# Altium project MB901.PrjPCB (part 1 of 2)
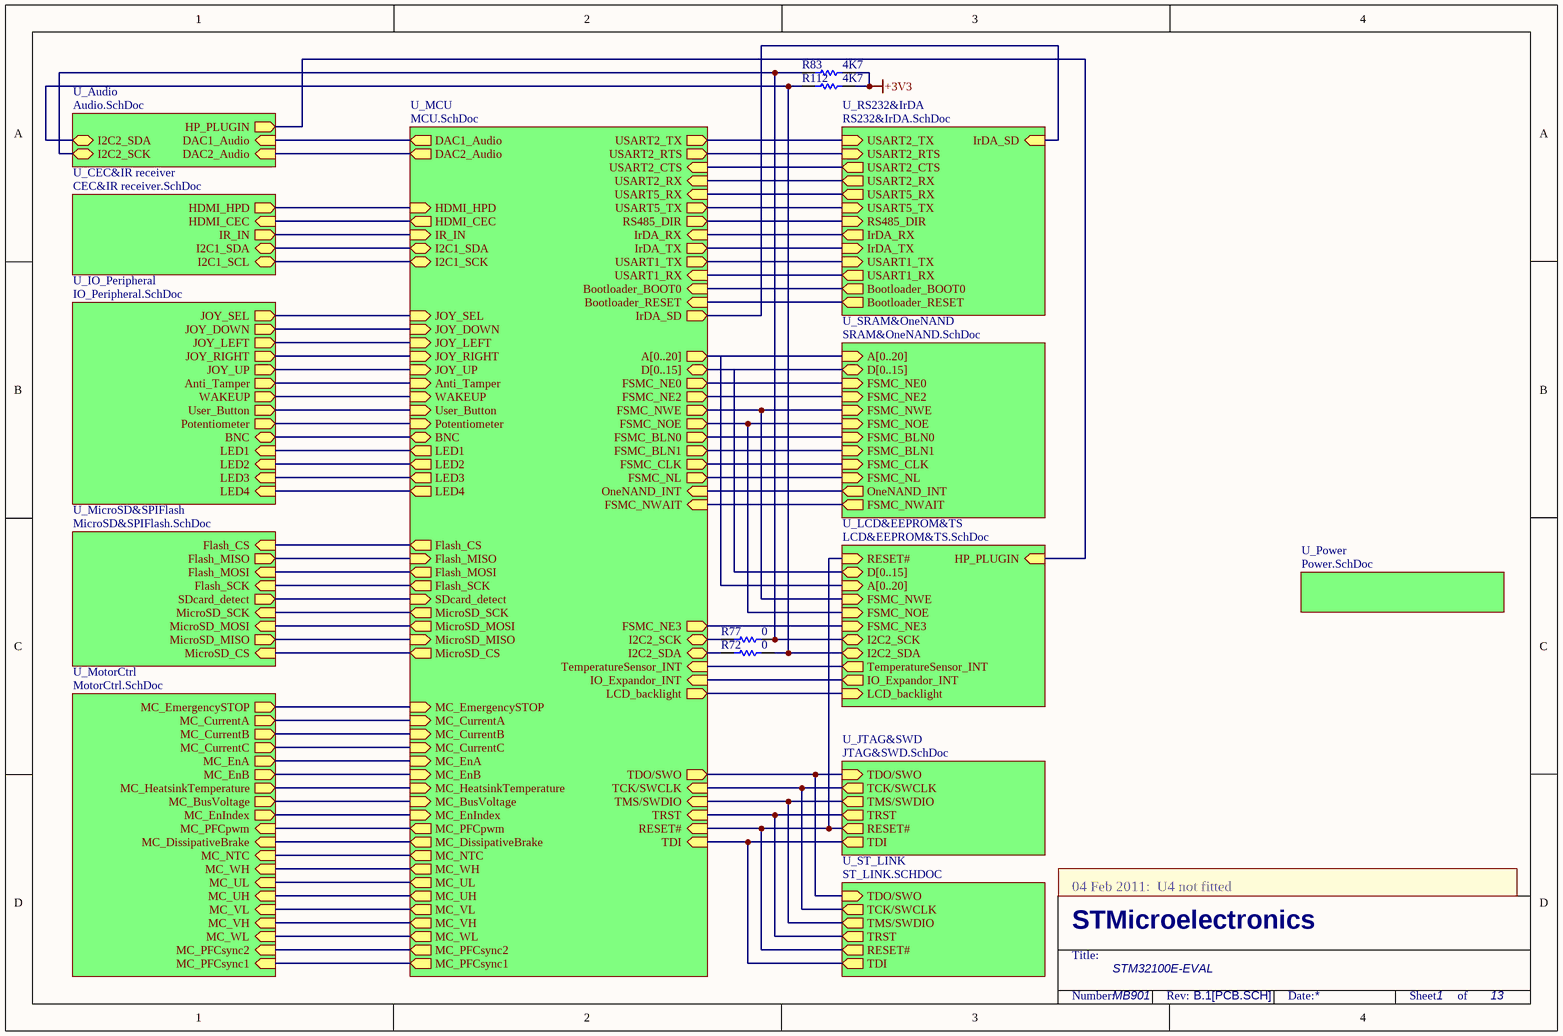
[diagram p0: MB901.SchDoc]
13 sheets, 331 parts. Net scope: hierarchical (ports join the sheet entries above them; power ports are global).
Board file: MB901.PCBDOC
Sheets:
  MB901.SchDoc
    U_Audio = Audio.SchDoc
    U_CEC&IR receiver = CEC&IR receiver.SchDoc
    U_IO_Peripheral = IO_Peripheral.SchDoc
    U_JTAG&SWD = JTAG&SWD.SchDoc
    U_LCD&EEPROM&TS = LCD&EEPROM&TS.SchDoc
    U_MCU = MCU.SchDoc
    U_MicroSD&SPIFlash = MicroSD&SPIFlash.SchDoc
    U_MotorCtrl = MotorCtrl.SchDoc
    U_Power = Power.SchDoc
    U_RS232&IrDA = RS232&IrDA.SchDoc
    U_SRAM&OneNAND = SRAM&OneNAND.SchDoc
    U_ST_LINK = ST_LINK.SCHDOC

## Sheet MB901.SchDoc
size A4; Revision: B.1[PCB.SCH]

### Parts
R72  0  [0603R]
R77  0  [0603R]
R83  4K7  [0603R]
R112  4K7  [0603R]

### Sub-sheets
U_Audio = Audio.SchDoc: DAC2_Audio (in), DAC1_Audio (in), I2C2_SCK (bidir), I2C2_SDA (bidir), HP_PLUGIN (out)
U_CEC&IR receiver = CEC&IR receiver.SchDoc: HDMI_CEC (in), I2C1_SCL (bidir), I2C1_SDA (bidir), HDMI_HPD (out), IR_IN (out)
U_IO_Peripheral = IO_Peripheral.SchDoc: JOY_SEL (out), JOY_DOWN (out), JOY_LEFT (out), JOY_RIGHT (out), JOY_UP (out), Anti_Tamper (out), WAKEUP (out), User_Button (out), LED4 (in), LED3 (in), LED1 (in), LED2 (in), BNC (bidir), Potentiometer (out)
U_JTAG&SWD = JTAG&SWD.SchDoc: TDI (out), RESET# (out), TRST (out), TMS/SWDIO (out), TCK/SWCLK (out), TDO/SWO (in)
U_LCD&EEPROM&TS = LCD&EEPROM&TS.SchDoc: RESET# (in), D[0..15] (bidir), A[0..20] (in), FSMC_NWE (in), FSMC_NOE (in), FSMC_NE3 (in), IO_Expandor_INT (out), I2C2_SCK (bidir), I2C2_SDA (bidir), TemperatureSensor_INT (out), LCD_backlight (in), HP_PLUGIN (in)
U_MCU = MCU.SchDoc: TDI (in), TMS/SWDIO (in), TCK/SWCLK (in), USART2_RX (in), USART2_TX (out), USART2_RTS (out), USART2_CTS (in), USART1_TX (out), USART1_RX (in), MC_EmergencySTOP (in), MC_UL (out), MC_DissipativeBrake (out), MC_EnA (in), MC_EnB (in), MC_EnIndex (in), WAKEUP (in), Flash_SCK (out), Flash_MISO (in), Flash_MOSI (out), BNC (bidir), TRST (in), TDO/SWO (out), MC_PFCsync1 (out), MC_WL (out), MC_VL (out), MC_NTC (out), MC_PFCpwm (out), Flash_CS (out), TemperatureSensor_INT (in), I2C2_SCK (bidir), I2C2_SDA (bidir), IrDA_RX (in), IrDA_TX (out), MC_CurrentA (in), MC_CurrentB (in), MC_CurrentC (in), MC_VH (out), MC_UH (out), MC_WH (out), MC_BusVoltage (in), MC_HeatsinkTemperature (in), Potentiometer (in), Anti_Tamper (in), RESET# (in), MC_PFCsync2 (out), FSMC_NE0 (out), FSMC_NWE (out), FSMC_NOE (out), FSMC_NWAIT (in), FSMC_BLN0 (out), User_Button (in), LED3 (out), LED1 (out), LED2 (out), JOY_SEL (in), JOY_DOWN (in), JOY_LEFT (in), JOY_RIGHT (in), JOY_UP (in), FSMC_NE2 (out), LED4 (out), D[0..15] (bidir), A[0..20] (out), FSMC_NE3 (out), FSMC_BLN1 (out), Bootloader_BOOT0 (in), Bootloader_RESET (in), MicroSD_SCK (out), MicroSD_MOSI (out), MicroSD_MISO (in), MicroSD_CS (out), IR_IN (in), USART5_RX (in), USART5_TX (out), HDMI_CEC (out), HDMI_HPD (in), RS485_DIR (out), FSMC_CLK (out), FSMC_NL (out), SDcard_detect (in), IO_Expandor_INT (in), OneNAND_INT (in), I2C1_SCK (bidir), I2C1_SDA (bidir), DAC2_Audio (out), DAC1_Audio (out), LCD_backlight (out), IrDA_SD (out)
U_MicroSD&SPIFlash = MicroSD&SPIFlash.SchDoc: Flash_CS (in), Flash_SCK (in), Flash_MISO (out), Flash_MOSI (in), MicroSD_CS (in), MicroSD_SCK (in), MicroSD_MOSI (in), MicroSD_MISO (out), SDcard_detect (out)
U_MotorCtrl = MotorCtrl.SchDoc: MC_EmergencySTOP (out), MC_CurrentA (out), MC_CurrentB (out), MC_CurrentC (out), MC_PFCsync1 (in), MC_PFCsync2 (in), MC_WL (in), MC_VH (in), MC_VL (in), MC_UH (in), MC_UL (in), MC_WH (in), MC_NTC (in), MC_DissipativeBrake (in), MC_PFCpwm (in), MC_EnA (out), MC_EnB (out), MC_HeatsinkTemperature (out), MC_BusVoltage (out), MC_EnIndex (out)
U_Power = Power.SchDoc: no entries
U_RS232&IrDA = RS232&IrDA.SchDoc: USART2_RX (out), USART2_TX (in), USART2_RTS (in), USART2_CTS (out), USART1_TX (in), USART1_RX (out), IrDA_RX (out), IrDA_TX (in), RS485_DIR (in), USART5_RX (out), USART5_TX (in), Bootloader_BOOT0 (out), Bootloader_RESET (out), IrDA_SD (in)
U_SRAM&OneNAND = SRAM&OneNAND.SchDoc: A[0..20] (in), D[0..15] (bidir), FSMC_NE0 (in), FSMC_NE2 (in), FSMC_NWE (in), FSMC_NOE (in), FSMC_BLN0 (in), FSMC_BLN1 (in), FSMC_NWAIT (out), FSMC_CLK (in), FSMC_NL (in), OneNAND_INT (out)
U_ST_LINK = ST_LINK.SCHDOC: TDI (out), TRST (out), TMS/SWDIO (out), TCK/SWCLK (out), TDO/SWO (in), RESET# (out)

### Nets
+3V3: R83.1 R112.1
PA0: sheet U_IO_Peripheral/WAKEUP, sheet U_MCU/WAKEUP
PA1: sheet U_MCU/USART2_RTS, sheet U_MCU/MC_EnB, sheet U_MotorCtrl/MC_EnB, sheet U_RS232&IrDA/USART2_RTS
PA2: sheet U_MCU/USART2_TX, sheet U_MCU/MC_EnIndex, sheet U_MotorCtrl/MC_EnIndex, sheet U_RS232&IrDA/USART2_TX
PA3: sheet U_MCU/USART2_RX, sheet U_RS232&IrDA/USART2_RX
PA4: sheet U_Audio/DAC1_Audio, sheet U_IO_Peripheral/BNC, sheet U_MCU/BNC, sheet U_MCU/DAC1_Audio
PA5: sheet U_Audio/DAC2_Audio, sheet U_MCU/Flash_SCK, sheet U_MCU/DAC2_Audio, sheet U_MicroSD&SPIFlash/Flash_SCK
PA6: sheet U_MCU/Flash_MISO, sheet U_MicroSD&SPIFlash/Flash_MISO
PA7: sheet U_MCU/MC_UL, sheet U_MCU/Flash_MOSI, sheet U_MicroSD&SPIFlash/Flash_MOSI, sheet U_MotorCtrl/MC_UL
PA8: sheet U_MCU/MC_UH, sheet U_MotorCtrl/MC_UH
PA9: sheet U_MCU/USART1_TX, sheet U_MCU/MC_VH, sheet U_MotorCtrl/MC_VH, sheet U_RS232&IrDA/USART1_TX
PA11: sheet U_MCU/IrDA_SD, sheet U_RS232&IrDA/IrDA_SD
PA12: sheet U_LCD&EEPROM&TS/IO_Expandor_INT, sheet U_MCU/IO_Expandor_INT
PA13: sheet U_JTAG&SWD/TMS/SWDIO, sheet U_MCU/TMS/SWDIO, sheet U_ST_LINK/TMS/SWDIO
PA14: sheet U_JTAG&SWD/TCK/SWCLK, sheet U_MCU/TCK/SWCLK, sheet U_ST_LINK/TCK/SWCLK
PA15: sheet U_JTAG&SWD/TDI, sheet U_MCU/TDI, sheet U_ST_LINK/TDI
PB0: sheet U_MCU/MC_VL, sheet U_MotorCtrl/MC_VL
PB1: sheet U_MCU/MC_WL, sheet U_MotorCtrl/MC_WL
PB3: sheet U_JTAG&SWD/TDO/SWO, sheet U_MCU/TDO/SWO, sheet U_ST_LINK/TDO/SWO
PB4: sheet U_JTAG&SWD/TRST, sheet U_MCU/TRST, sheet U_MCU/MC_PFCsync1, sheet U_MotorCtrl/MC_PFCsync1, sheet U_ST_LINK/TRST
PB5: sheet U_MCU/MC_PFCpwm, sheet U_MotorCtrl/MC_PFCpwm
PB6: sheet U_CEC&IR receiver/I2C1_SCL, sheet U_MCU/I2C1_SCK
PB8: sheet U_CEC&IR receiver/HDMI_CEC, sheet U_MCU/HDMI_CEC
PB9: sheet U_CEC&IR receiver/HDMI_HPD, sheet U_MCU/HDMI_HPD
PB10: R77.2 ; sheet U_MCU/I2C2_SCK
PB11: R72.2 ; sheet U_MCU/I2C2_SDA
PB12: sheet U_MCU/MC_NTC, sheet U_MotorCtrl/MC_NTC
PB13: sheet U_MCU/MicroSD_SCK, sheet U_MicroSD&SPIFlash/MicroSD_SCK
PB14: sheet U_MCU/MicroSD_MISO, sheet U_MicroSD&SPIFlash/MicroSD_MISO
PB15: sheet U_MCU/MicroSD_MOSI, sheet U_MicroSD&SPIFlash/MicroSD_MOSI
PC0: sheet U_MCU/MC_BusVoltage, sheet U_MotorCtrl/MC_BusVoltage
PC1: sheet U_MCU/MC_CurrentA, sheet U_MotorCtrl/MC_CurrentA
PC2: sheet U_MCU/MC_CurrentB, sheet U_MotorCtrl/MC_CurrentB
PC3: sheet U_MCU/MC_CurrentC, sheet U_MotorCtrl/MC_CurrentC
PC4: sheet U_IO_Peripheral/Potentiometer, sheet U_MCU/Potentiometer
PC5: sheet U_MCU/MC_HeatsinkTemperature, sheet U_MotorCtrl/MC_HeatsinkTemperature
PC6: sheet U_CEC&IR receiver/IR_IN, sheet U_MCU/IR_IN
PC7: sheet U_LCD&EEPROM&TS/LCD_backlight, sheet U_MCU/LCD_backlight
PC8: sheet U_MCU/MC_DissipativeBrake, sheet U_MotorCtrl/MC_DissipativeBrake
PC9: sheet U_MCU/RS485_DIR, sheet U_RS232&IrDA/RS485_DIR
PC10: sheet U_MCU/IrDA_TX, sheet U_RS232&IrDA/IrDA_TX
PC11: sheet U_MCU/IrDA_RX, sheet U_RS232&IrDA/IrDA_RX
PC12: sheet U_MCU/USART5_TX, sheet U_RS232&IrDA/USART5_TX
PC13: sheet U_IO_Peripheral/Anti_Tamper, sheet U_MCU/Anti_Tamper
PD2: sheet U_MCU/MC_PFCsync2, sheet U_MotorCtrl/MC_PFCsync2
PD3: sheet U_MCU/FSMC_CLK, sheet U_SRAM&OneNAND/FSMC_CLK
PD4: sheet U_LCD&EEPROM&TS/FSMC_NOE, sheet U_MCU/FSMC_NOE, sheet U_SRAM&OneNAND/FSMC_NOE
PD5: sheet U_LCD&EEPROM&TS/FSMC_NWE, sheet U_MCU/FSMC_NWE, sheet U_SRAM&OneNAND/FSMC_NWE
PD6: sheet U_MCU/FSMC_NWAIT, sheet U_SRAM&OneNAND/FSMC_NWAIT
PD7: sheet U_MCU/FSMC_NE0, sheet U_SRAM&OneNAND/FSMC_NE0
PE0: sheet U_MCU/FSMC_BLN0, sheet U_SRAM&OneNAND/FSMC_BLN0
PE1: sheet U_MCU/FSMC_BLN1, sheet U_SRAM&OneNAND/FSMC_BLN1
PE6: sheet U_MCU/Flash_CS, sheet U_MicroSD&SPIFlash/Flash_CS
PF6: sheet U_IO_Peripheral/LED1, sheet U_MCU/LED1
PF7: sheet U_IO_Peripheral/LED2, sheet U_MCU/LED2
PF8: sheet U_IO_Peripheral/LED3, sheet U_MCU/LED3
PF9: sheet U_IO_Peripheral/LED4, sheet U_MCU/LED4
PF10: sheet U_MCU/OneNAND_INT, sheet U_SRAM&OneNAND/OneNAND_INT
PF11: sheet U_MCU/SDcard_detect, sheet U_MicroSD&SPIFlash/SDcard_detect
PG6: sheet U_MCU/MicroSD_CS, sheet U_MicroSD&SPIFlash/MicroSD_CS
PG7: sheet U_IO_Peripheral/JOY_SEL, sheet U_MCU/JOY_SEL
PG8: sheet U_IO_Peripheral/User_Button, sheet U_MCU/User_Button
PG10: sheet U_MCU/FSMC_NE2, sheet U_SRAM&OneNAND/FSMC_NE2
PG11: sheet U_IO_Peripheral/JOY_DOWN, sheet U_MCU/JOY_DOWN
PG12: sheet U_LCD&EEPROM&TS/FSMC_NE3, sheet U_MCU/FSMC_NE3
PG13: sheet U_IO_Peripheral/JOY_RIGHT, sheet U_MCU/JOY_RIGHT
PG14: sheet U_IO_Peripheral/JOY_LEFT, sheet U_MCU/JOY_LEFT
PG15: sheet U_IO_Peripheral/JOY_UP, sheet U_MCU/JOY_UP
RESET#: sheet U_JTAG&SWD/RESET#, sheet U_LCD&EEPROM&TS/RESET#, sheet U_MCU/RESET#, sheet U_ST_LINK/RESET#
NetC13_2: sheet U_MCU/MC_EnA, sheet U_MotorCtrl/MC_EnA
NetCN1_11: sheet U_MCU/MC_WH, sheet U_MotorCtrl/MC_WH
NetCN11_5: sheet U_Audio/HP_PLUGIN, sheet U_LCD&EEPROM&TS/HP_PLUGIN
NetJP3_2: sheet U_MCU/MC_EmergencySTOP, sheet U_MotorCtrl/MC_EmergencySTOP
NetJP4_3: sheet U_MCU/USART2_CTS, sheet U_RS232&IrDA/USART2_CTS
NetJP5_1: sheet U_MCU/USART1_RX, sheet U_RS232&IrDA/USART1_RX
NetJP6_1: sheet U_MCU/FSMC_NL, sheet U_SRAM&OneNAND/FSMC_NL
NetJP6_3: sheet U_CEC&IR receiver/I2C1_SDA, sheet U_MCU/I2C1_SDA
NetJP7_2: sheet U_MCU/Bootloader_RESET, sheet U_RS232&IrDA/Bootloader_RESET
NetJP8_2: sheet U_MCU/Bootloader_BOOT0, sheet U_RS232&IrDA/Bootloader_BOOT0
NetJP9_1: sheet U_MCU/USART5_RX, sheet U_RS232&IrDA/USART5_RX
NetJP11_2: sheet U_LCD&EEPROM&TS/TemperatureSensor_INT, sheet U_MCU/TemperatureSensor_INT
NetR72_1: R72.1 R112.2 ; sheet U_Audio/I2C2_SDA, sheet U_LCD&EEPROM&TS/I2C2_SDA
NetR77_1: R77.1 R83.2 ; sheet U_Audio/I2C2_SCK, sheet U_LCD&EEPROM&TS/I2C2_SCK

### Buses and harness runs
bus sheet U_LCD&EEPROM&TS/A[0..20] = sheet U_MCU/A[0..20] = sheet U_SRAM&OneNAND/A[0..20]
bus sheet U_LCD&EEPROM&TS/D[0..15] = sheet U_MCU/D[0..15] = sheet U_SRAM&OneNAND/D[0..15]

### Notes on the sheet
- 04 Feb 2011:  U4 not fitted
- STM32100E-EVAL
- MB901
- 1
- 13

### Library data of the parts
R72 R77 R83 R112 = Res1: Resistor; Value: 1K

## Sheet Audio.SchDoc
size A4; Revision: B.1(PCB.SCH)
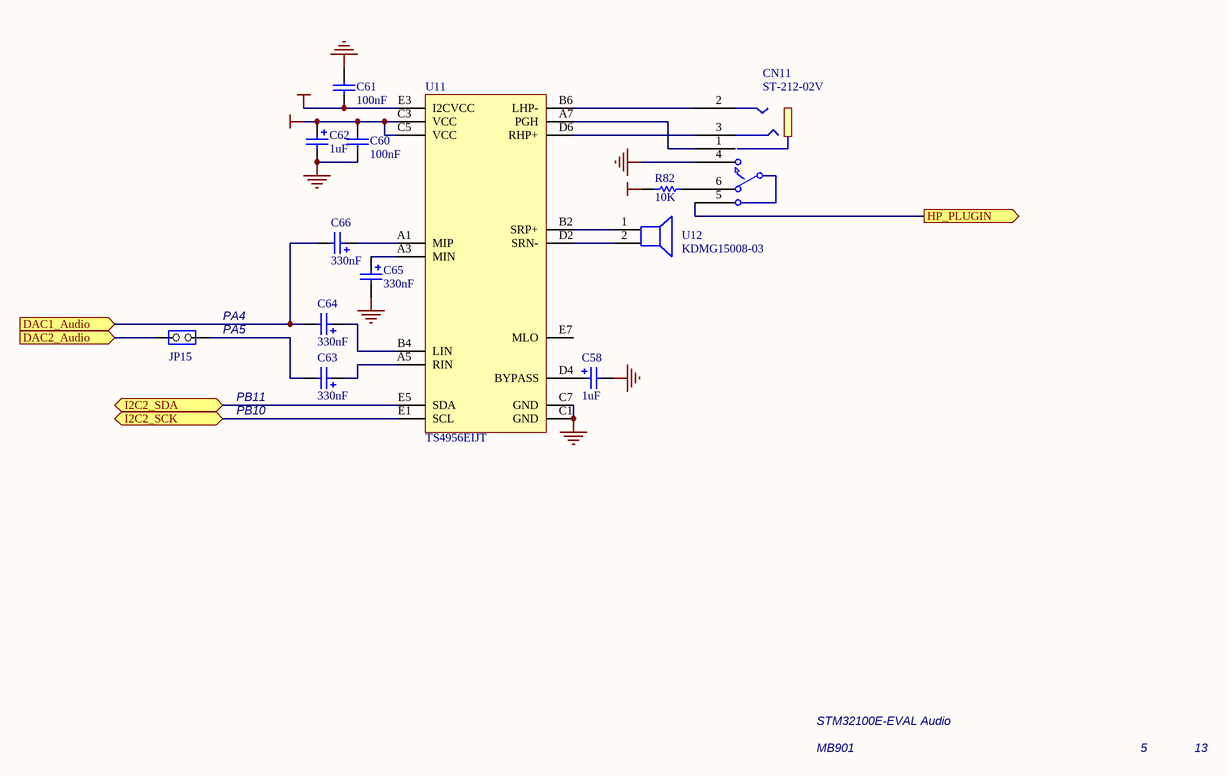
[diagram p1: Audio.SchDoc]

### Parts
C58  1uF  [TAN-A]
C60  100nF  [0402C]
C61  100nF  [0402C]
C62  1uF  [TAN-A]
C63  330nF  [0603C]
C64  330nF  [0603C]
C65  330nF  [0603C]
C66  330nF  [0603C]
CN11  ST-212-02V  [ST-212-02V]
JP15  (no value)  [SIP2]
R82  10K  [0402R]
U11  TS4956EIJT  [18-bump flip-chip]
U12  KDMG15008-03  [KS1508]

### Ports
DAC1_Audio (in), DAC2_Audio (in), HP_PLUGIN (out), I2C2_SCK (bidir), I2C2_SDA (bidir)

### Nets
+3V3: C61.1 R82.1 U11.E3(I2CVCC)
+5V: C60.1 C62.1 U11.C3(VCC) U11.C5(VCC)
GND: C58.2 C60.2 C61.2 C62.2 C65.2 CN11.4 U11.C1(GND) U11.C7(GND)
PA4: C64.2 C66.2 ; port DAC1_Audio
PA5: JP15.2(NO) ; port DAC2_Audio
NetC58_1: C58.1 U11.D4(BYPASS)
NetC63_1: C63.1 U11.A5(RIN)
NetC63_2: C63.2 JP15.1(COMMON)
NetC64_1: C64.1 U11.B4(LIN)
NetC65_1: C65.1 U11.A3(MIN)
NetC66_1: C66.1 U11.A1(MIP)
NetCN11_1: CN11.1 U11.A7(PGH)
NetCN11_2: CN11.2 U11.B6(LHP-)
NetCN11_3: CN11.3 U11.D6(RHP+)
NetCN11_5: CN11.5 ; port HP_PLUGIN
NetCN11_6: CN11.6 R82.2
NetR72_1: U11.E5(SDA) ; port I2C2_SDA
NetR77_1: U11.E1(SCL) ; port I2C2_SCK
NetU11_B2: U11.B2(SRP+) U12.1(+)
NetU11_D2: U11.D2(SRN-) U12.2(-)

Not connected (* = marked no-connect by the designer): U11 E7(MLO)

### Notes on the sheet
- (near JP15) PA5
- (near JP15) PA4
- PB11
- PB10
- STM32100E-EVAL Audio
- MB901
- 5
- 13

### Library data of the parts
C58 C62-C66 = Cap Pol1: Polarized Capacitor (Radial); Value: 10uF
C60 C61 = CAP: Capacitor
JP15 = JP2
R82 = res1: Resistor; Value: 1K
U12 = Speaker: Loudspeaker

## Sheet CEC&IR receiver.SchDoc
size A4; Revision: B.1(PCB.SCH)
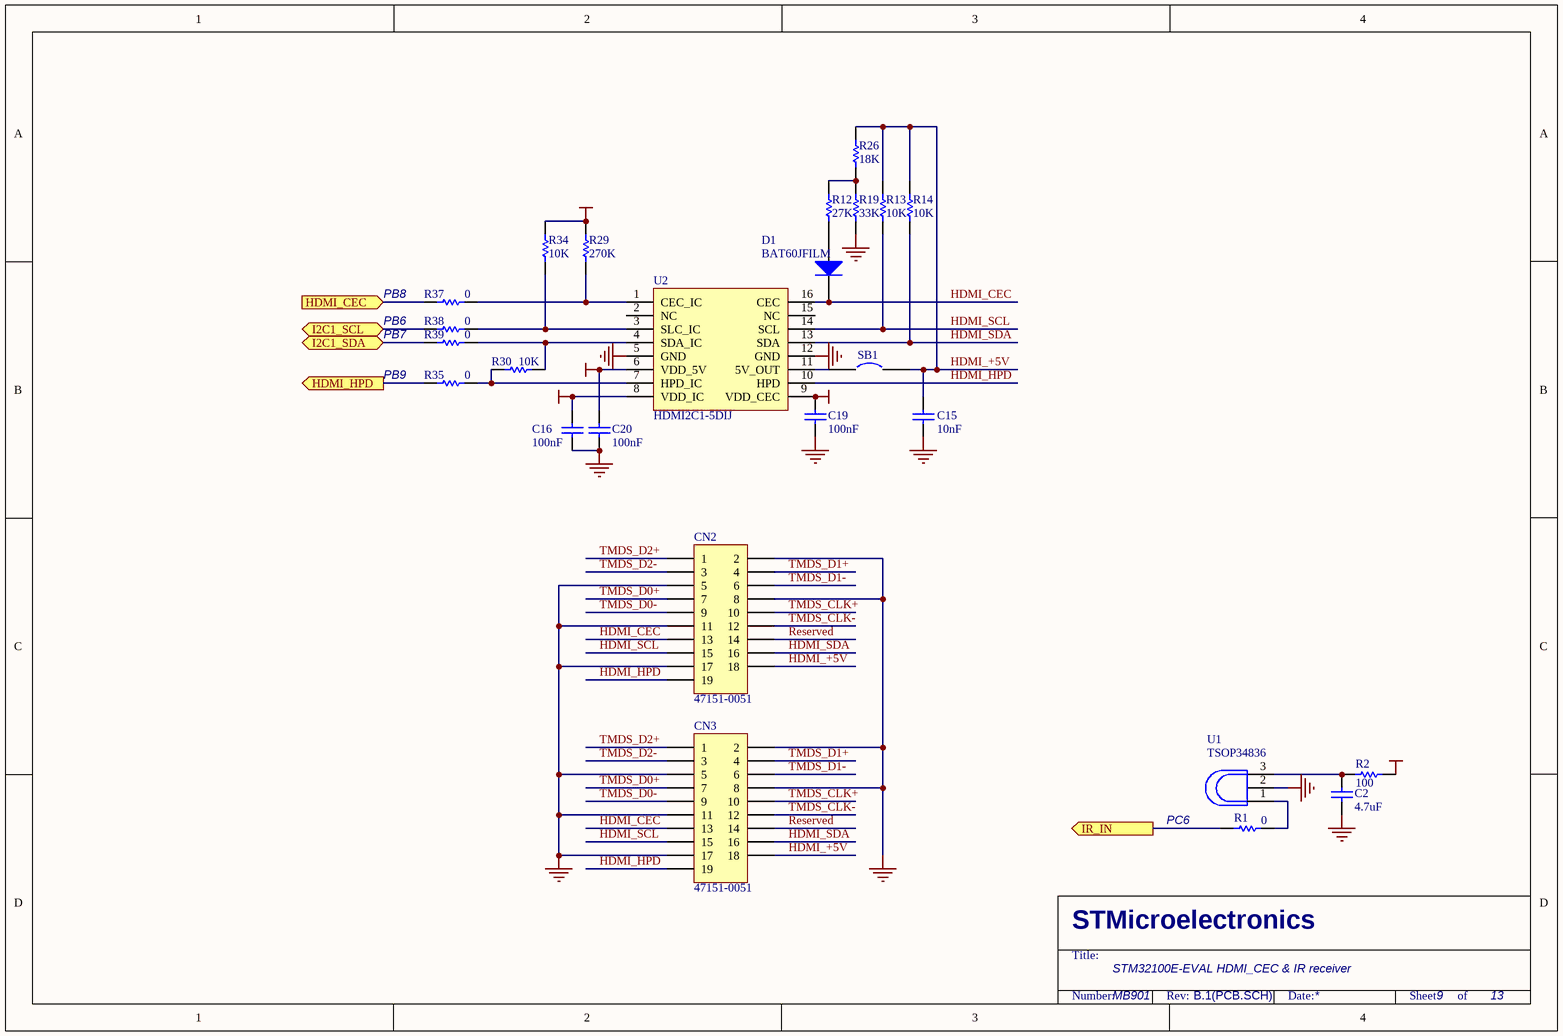
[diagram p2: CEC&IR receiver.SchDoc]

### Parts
C2  4.7uF  [1206C]
C15  10nF  [0603C]
C16  100nF  [0402C]
C19  100nF  [0402C]
C20  100nF  [0402C]
CN2  47151-0051  [0471510101]
CN3  47151-0051  [0471510101]
D1  BAT60JFILM  [SOD-323]
R1  0  [0603R]
R2  100  [0603R]
R12  27K  [0603R]
R13  10K  [0402R]
R14  10K  [0402R]
R19  33K  [0603R]
R26  18K  [0603R]
R29  270K  [0603R]
R30  10K  [0402R]
R34  10K  [0402R]
R35  0  [0603R]
R37  0  [0603R]
R38  0  [0603R]
R39  0  [0603R]
SB1  (no value)  [JP2_SMD]
U1  TSOP34836
U2  HDMI2C1-5DIJ  [QFN16(5*4)]

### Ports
HDMI_CEC (in), HDMI_HPD (out), I2C1_SCL (bidir), I2C1_SDA (bidir), IR_IN (out)

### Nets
+3V3: C16.1 C19.1 R2.2 R29.1 R34.1 U2.8(VDD_IC) U2.9(VDD_CEC)
+5V: C20.1 U2.6(VDD_5V)
GND: C2.2 C15.2 C16.2 C19.2 C20.2 CN2.2 CN2.5 CN2.8 CN2.11 CN2.17 CN3.2 CN3.5 CN3.8 CN3.11 CN3.17 R19.2 U1.2(GND) U2.5(GND) U2.12(GND)
HDMI_+5V: C15.1 CN2.18 CN3.18 R13.1 R14.1 R26.1 SB1.2
HDMI_CEC: CN2.13 CN3.13 D1.2(K) U2.16(CEC)
HDMI_HPD: CN2.19 CN3.19 U2.10(HPD)
HDMI_SCL: CN2.15 CN3.15 R13.2 U2.14(SCL)
HDMI_SDA: CN2.16 CN3.16 R14.2 U2.13(SDA)
PB6: R38.2 ; port I2C1_SCL
PB8: R37.2 ; port HDMI_CEC
PB9: R35.2 ; port HDMI_HPD
PC6: R1.1 ; port IR_IN
Reserved: CN2.14 CN3.14
TMDS_CLK+: CN2.10 CN3.10
TMDS_CLK-: CN2.12 CN3.12
TMDS_D0+: CN2.7 CN3.7
TMDS_D0-: CN2.9 CN3.9
TMDS_D1+: CN2.4 CN3.4
TMDS_D1-: CN2.6 CN3.6
TMDS_D2+: CN2.1 CN3.1
TMDS_D2-: CN2.3 CN3.3
NetC2_1: C2.1 R2.1 U1.3(Vs)
NetD1_1: D1.1(A) R12.2
NetJP6_3: R39.2 ; port I2C1_SDA
NetR1_2: R1.2 U1.1(OUT)
NetR12_1: R12.1 R19.1 R26.2
NetR29_2: R29.2 R37.1 U2.1(CEC_IC)
NetR30_1: R30.1 R35.1 U2.7(HPD_IC)
NetR30_2: R30.2 R39.1 U2.4(SDA_IC)
NetR34_2: R34.2 R38.1 U2.3(SLC_IC)
NetSB1_1: SB1.1 U2.11(5V_OUT)

Not connected (* = marked no-connect by the designer): U2 2(NC) 15(NC)

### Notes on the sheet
- PB8
- PB6
- PB7
- PB9
- PC6
- STM32100E-EVAL HDMI_CEC & IR receiver
- MB901
- 9
- 13

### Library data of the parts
C2 C16 C19 C20 = Cap: Capacitor; Value: 10nF
C15 = Cap: Capacitor
CN2 CN3 = Header 10X2: Header, 10-Pin, Dual row
D1 = Diode: Default Diode; Code - JEDEC: DO-214-AB
R1 R2 R12-R14 R19 R26 R29 R30 R34 R35 R37-R39 = Res1: Resistor; Value: 1K
SB1 = Circuit Breaker
U1 = TSOP34838

## Sheet IO_Peripheral.SchDoc
size A4; Revision: B.1(PCB.SCH)
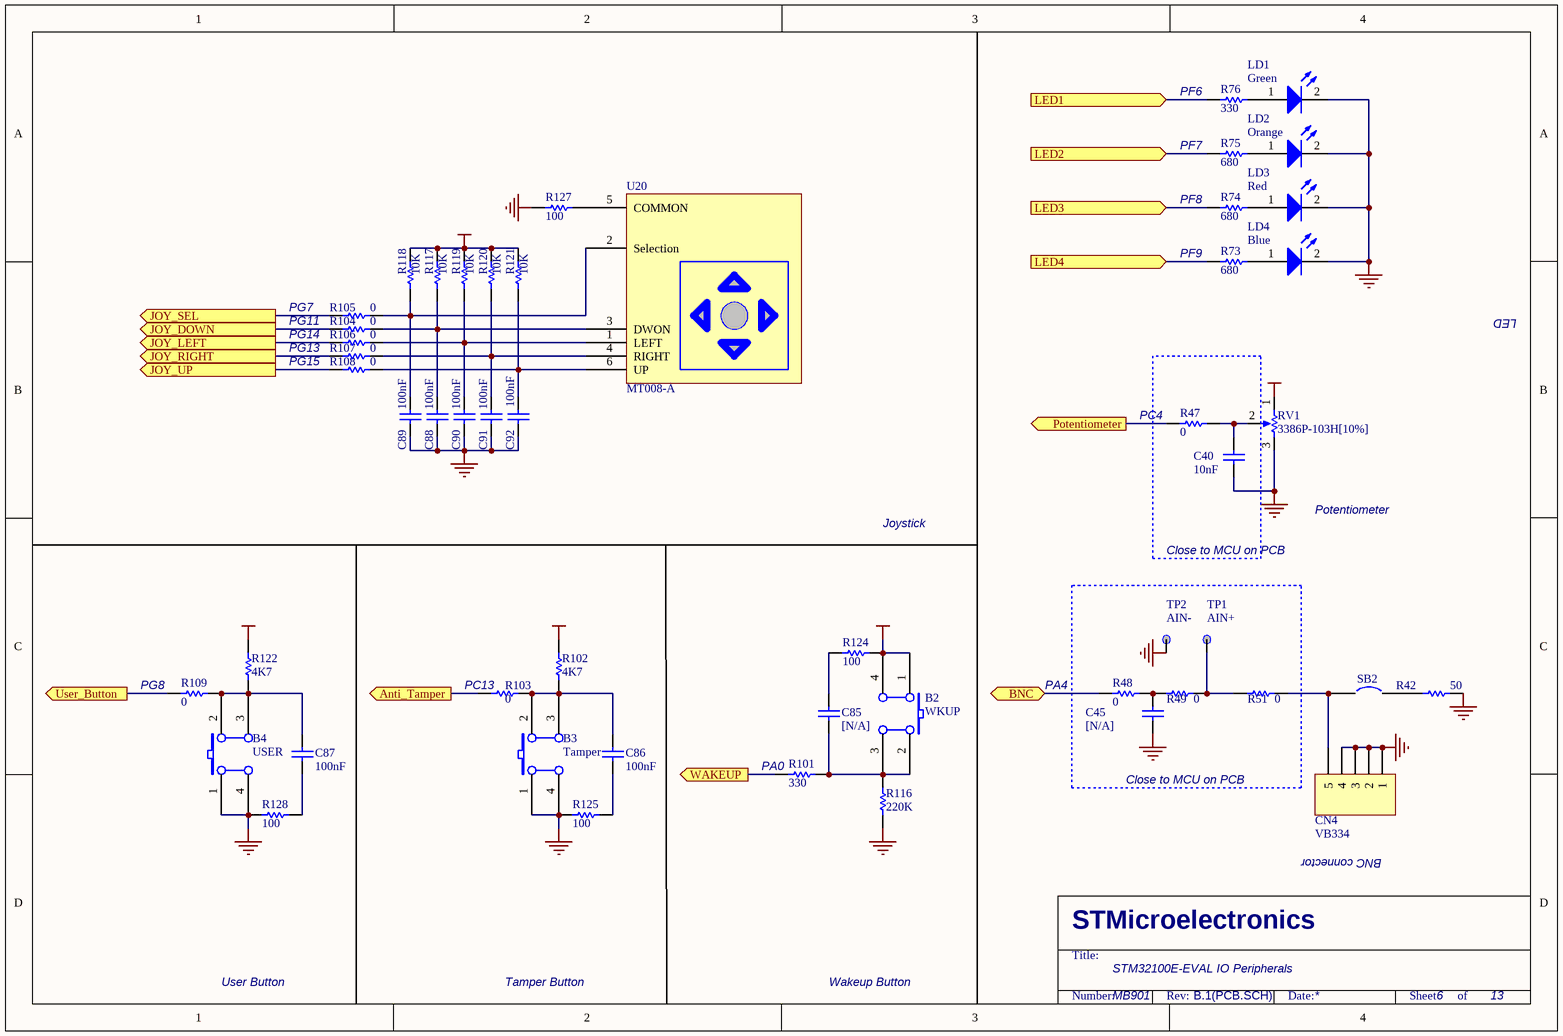
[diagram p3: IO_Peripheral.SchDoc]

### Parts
B2  WKUP  [PB10]
B3  Tamper  [PB10]
B4  USER  [PB10]
C40  10nF  [0603C]
C45  [N/A]  [0603C]
C85  [N/A]  [0603C]
C86  100nF  [0402C]
C87  100nF  [0402C]
C88  100nF  [0402C]
C89  100nF  [0402C]
C90  100nF  [0402C]
C91  100nF  [0402C]
C92  100nF  [0402C]
CN4  VB334  [VB334]
LD1  Green  [0603D]
LD2  Orange  [0603D]
LD3  Red  [0603D]
LD4  Blue  [0603D]
R42  50  [0603R]
R47  0  [0603R]
R48  0  [0603R]
R49  0  [0603R]
R51  0  [0603R]
R73  680  [0603R]
R74  680  [0603R]
R75  680  [0603R]
R76  330  [0603R]
R101  330  [0603R]
R102  4K7  [0603R]
R103  0  [0603R]
R104  0  [0603R]
R105  0  [0603R]
R106  0  [0603R]
R107  0  [0603R]
R108  0  [0603R]
R109  0  [0603R]
R116  220K  [0603R]
R117  10K  [0402R]
R118  10K  [0402R]
R119  10K  [0402R]
R120  10K  [0402R]
R121  10K  [0402R]
R122  4K7  [0603R]
R124  100  [0603R]
R125  100  [0603R]
R127  100  [0603R]
R128  100  [0603R]
RV1  3386P-103H[10%]  [3296W]
SB2  (no value)  [JP2_SMD]
TP1  AIN+  [TP]
TP2  AIN-  [TP]
U20  MT008-A  [JOY]

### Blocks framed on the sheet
Close to MCU on PCB: C40 R47
Close to MCU on PCB: C45 R48 R49 R51 TP1 TP2

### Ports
Anti_Tamper (out), BNC (bidir), JOY_DOWN (out), JOY_LEFT (out), JOY_RIGHT (out), JOY_SEL (out), JOY_UP (out), LED1 (in), LED2 (in), LED3 (in), LED4 (in), Potentiometer (out), User_Button (out), WAKEUP (out)

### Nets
+3V3: B2.1(A0) B2.4(A1) R102.2 R117.2 R118.1 R119.2 R120.2 R121.2 R122.2 R124.1 RV1.1(TOP)
GND: B3.1(A0) B3.4(A1) B4.1(A0) B4.4(A1) C40.1 C45.1 C88.1 C89.1 C90.1 C91.1 C92.1 CN4.1 CN4.2 CN4.3 CN4.4 LD1.2(K) LD2.2(K) LD3.2(K) LD4.2(K) R42.2 R116.2 R125.1 R127.1 R128.1 RV1.3(BOT) TP2.1
PA0: R101.2 ; port WAKEUP
PA4: R48.1 ; port BNC
PC4: R47.1 ; port Potentiometer
PC13: R103.2 ; port Anti_Tamper
PF6: R76.2 ; port LED1
PF7: R75.2 ; port LED2
PF8: R74.2 ; port LED3
PF9: R73.2 ; port LED4
PG7: R105.2 ; port JOY_SEL
PG8: R109.2 ; port User_Button
PG11: R104.2 ; port JOY_DOWN
PG13: R107.2 ; port JOY_RIGHT
PG14: R106.2 ; port JOY_LEFT
PG15: R108.2 ; port JOY_UP
NetB2_2: B2.2(B0) B2.3(B1) C85.2 R101.1 R116.1
NetB3_2: B3.2(B0) B3.3(B1) C86.2 R102.1 R103.1
NetB4_2: B4.2(B0) B4.3(B1) C87.2 R109.1 R122.1
NetC40_2: C40.2 R47.2 RV1.2(TAP)
NetC45_2: C45.2 R48.2 R49.1
NetC85_1: C85.1 R124.2
NetC86_1: C86.1 R125.2
NetC87_1: C87.1 R128.2
NetC88_2: C88.2 R104.1 R117.1 U20.3(DWON)
NetC89_2: C89.2 R105.1 R118.2 U20.2(Selection)
NetC90_2: C90.2 R106.1 R119.1 U20.1(LEFT)
NetC91_2: C91.2 R107.1 R120.1 U20.4(RIGHT)
NetC92_2: C92.2 R108.1 R121.1 U20.6(UP)
NetCN4_5: CN4.5 R51.2 SB2.1
NetLD1_1: LD1.1(A) R76.1
NetLD2_1: LD2.1(A) R75.1
NetLD3_1: LD3.1(A) R74.1
NetLD4_1: LD4.1(A) R73.1
NetR42_1: R42.1 SB2.2
NetR49_2: R49.2 R51.1 TP1.1
NetR127_2: R127.2 U20.5(COMMON)

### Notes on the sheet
- (near R76) PF6
- (near R75) PF7
- (near R74) PF8
- PG7
- (near R73) PF9
- LED
- PG11
- PG14
- PG13
- PG15
- (near R47) PC4
- Potentiometer
- Joystick
- (near R109) PG8
- (near R103) PC13
- (near R48) PA4
- (near R101) PA0
- BNC connector
- User Button
- Tamper Button
- Wakeup Button
- STM32100E-EVAL IO Peripherals
- MB901
- 6
- 13

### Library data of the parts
B2-B4 = SW PUSHBUTTON: SE PUSHBUTTON
C40 C85-C92 = CAP: Capacitor; Value: 100pF
C45 = cap: Capacitor; Value: 100pF
CN4 = Header 5: Header, 5-Pin
LD1-LD4 = LED2: Typical RED, GREEN, YELLOW, AMBER GaAs LED
R42 R47-R49 R51 R73-R76 R101 R103-R109 R117-R121 R124 R125 R127 R128 = Res1: Resistor; Value: 1K
R102 R116 R122 = res1: Resistor; Value: 1K
RV1 = RV
SB2 = Circuit Breaker
TP1 TP2 = TP
U20 = MT-008A

## Sheet JTAG&SWD.SchDoc
size A4; Revision: B.1(PCB.SCH)
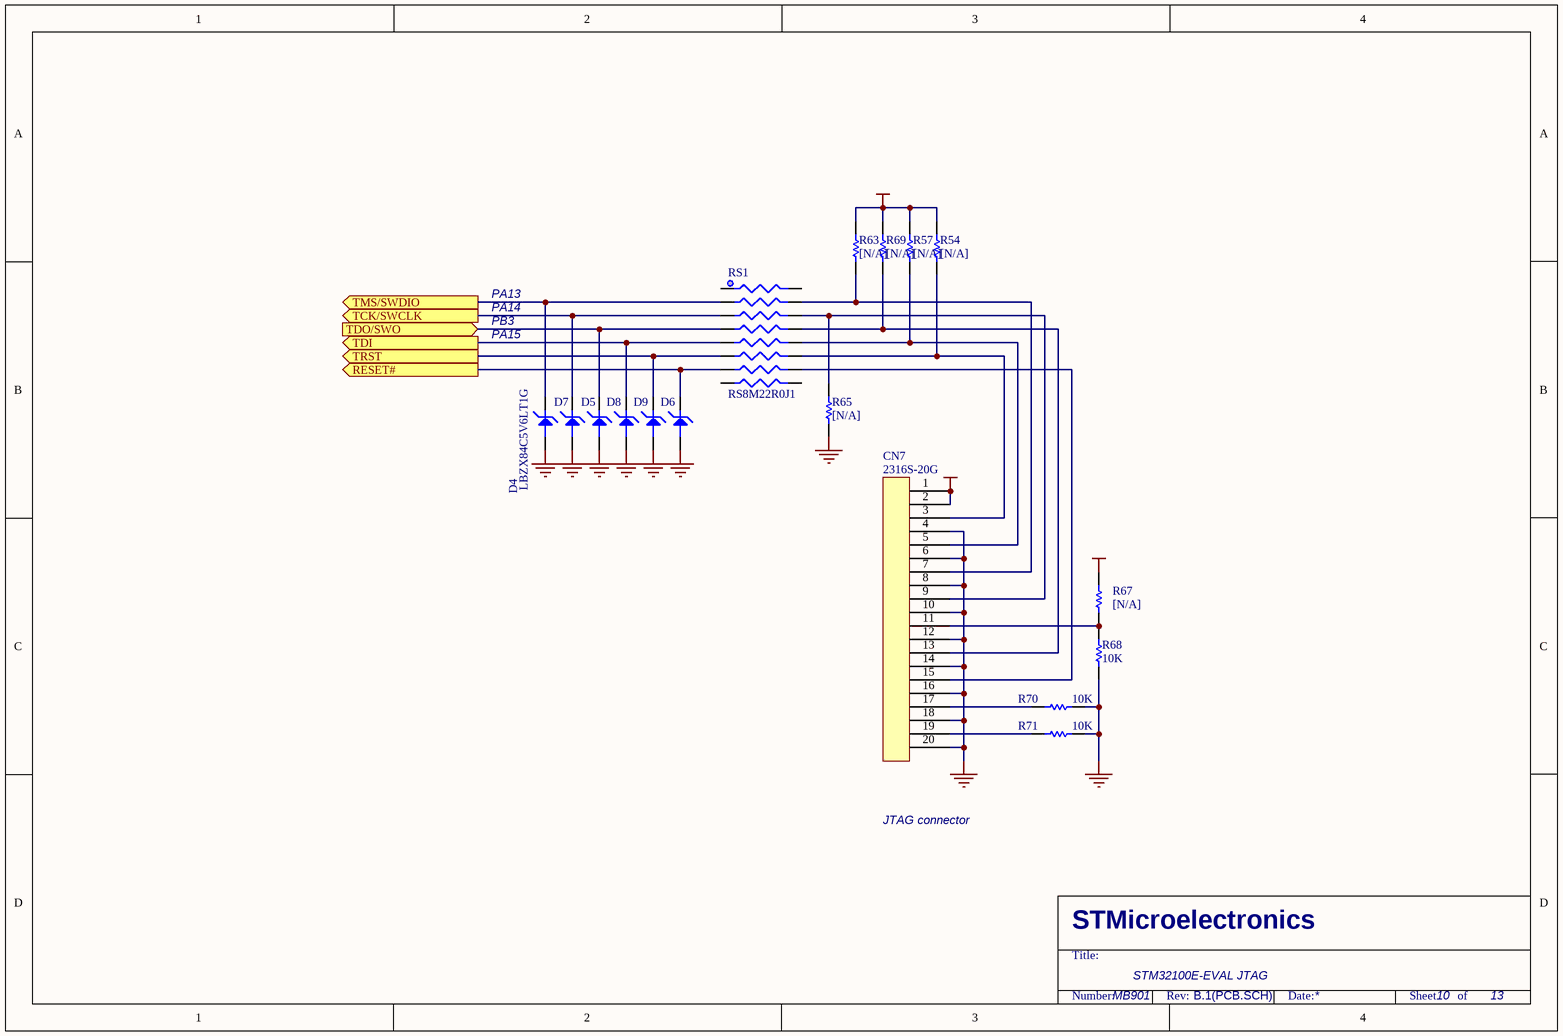
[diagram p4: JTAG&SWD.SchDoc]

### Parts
CN7  2316S-20G  [IDC20S]
D4  LBZX84C5V6LT1G  [SOT-23]
D5  LBZX84C5V6LT1G  [SOT-23]  (value not drawn)
D6  LBZX84C5V6LT1G  [SOT-23]  (value not drawn)
D7  LBZX84C5V6LT1G  [SOT-23]  (value not drawn)
D8  LBZX84C5V6LT1G  [SOT-23]  (value not drawn)
D9  LBZX84C5V6LT1G  [SOT-23]  (value not drawn)
R54  [N/A]  [0603R]
R57  [N/A]  [0603R]
R63  [N/A]  [0603R]
R65  [N/A]  [0603R]
R67  [N/A]  [0603R]
R68  10K  [0402R]
R69  [N/A]  [0603R]
R70  10K  [0402R]
R71  10K  [0402R]
RS1  RS8M22R0J1  [RES8B_0402]

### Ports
RESET# (out), TCK/SWCLK (out), TDI (out), TDO/SWO (in), TMS/SWDIO (out), TRST (out)

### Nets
+3V3: CN7.1 CN7.2 R54.2 R57.2 R63.2 R67.2 R69.2
GND: CN7.4 CN7.6 CN7.8 CN7.10 CN7.12 CN7.14 CN7.16 CN7.18 CN7.20 D4.2 D5.2 D6.2 D7.2 D8.2 D9.2 R65.1 R68.1 R70.1 R71.1
PA13: D4.3 RS1.3 ; port TMS/SWDIO
PA14: D7.3 RS1.5 ; port TCK/SWCLK
PA15: D8.3 RS1.9 ; port TDI
PB3: D5.3 RS1.7 ; port TDO/SWO
PB4: D9.3 RS1.11 ; port TRST
RESET#: D6.3 RS1.13 ; port RESET#
NetCN7_3: CN7.3 R54.1 RS1.12
NetCN7_5: CN7.5 R57.1 RS1.10
NetCN7_7: CN7.7 R63.1 RS1.4
NetCN7_9: CN7.9 R65.2 RS1.6
NetCN7_11: CN7.11 R67.1 R68.2
NetCN7_13: CN7.13 R69.1 RS1.8
NetCN7_15: CN7.15 RS1.14
NetCN7_17: CN7.17 R70.2
NetCN7_19: CN7.19 R71.2

Not connected (* = marked no-connect by the designer): RS1 1 2 15 16

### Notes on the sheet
- PA13
- PA14
- PB3
- PA15
- JTAG connector
- STM32100E-EVAL JTAG
- MB901
- 10
- 13

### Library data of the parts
CN7 = 20PIN1
D4-D9 = Z5V6
R54 R57 R63 R65 R67-R71 = Res1: Resistor; Value: 1K
RS1 = RES8B

## Sheet LCD&EEPROM&TS.SchDoc
size A4; Revision: B.1(PCB.SCH)
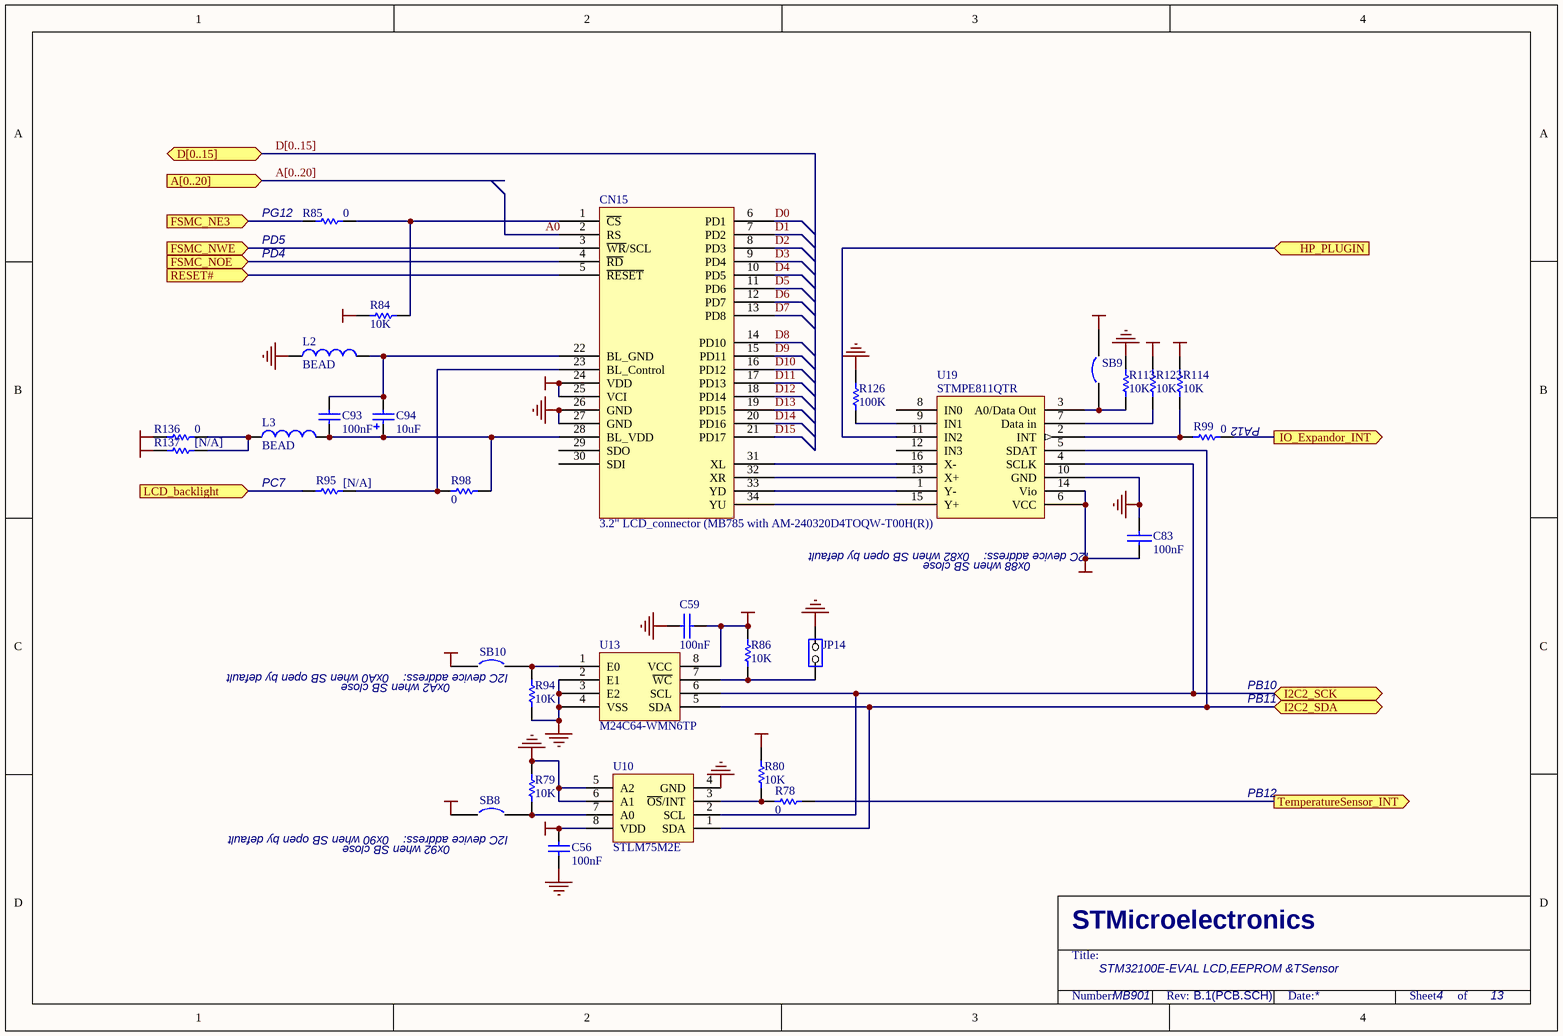
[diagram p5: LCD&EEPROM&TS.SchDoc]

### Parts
C56  100nF  [0402C]
C59  100nF  [0402C]
C83  100nF  [0402C]
C93  100nF  [0402C]
C94  10uF  [TAN-A]
CN15  3.2" LCD_connector (MB785 with AM-240320D4TOQW-T00H(R))  [AM240*320AA]
JP14  (no value)  [SIP2]
L2  BEAD  [0603L]
L3  BEAD  [0603L]
R78  0  [0603R]
R79  10K  [0402R]
R80  10K  [0402R]
R84  10K  [0402R]
R85  0  [0603R]
R86  10K  [0402R]
R94  10K  [0402R]
R95  [N/A]  [0603R]
R98  0  [0603R]
R99  0  [0603R]
R113  10K  [0402R]
R114  10K  [0402R]
R123  10K  [0402R]
R126  100K  [0603R]
R136  0  [0603R]
R137  [N/A]  [0603R]
SB8  (no value)  [JP2_SMD]
SB9  (no value)  [JP2_SMD]
SB10  (no value)  [JP2_SMD]
U10  STLM75M2E  [SO8]
U13  M24C64-WMN6TP  [SO8]
U19  STMPE811QTR  [QFN16(3X3)]

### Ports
A[0..20] (in), D[0..15] (bidir), FSMC_NE3 (in), FSMC_NOE (in), FSMC_NWE (in), HP_PLUGIN (in), I2C2_SCK (bidir), I2C2_SDA (bidir), IO_Expandor_INT (out), LCD_backlight (in), RESET# (in), TemperatureSensor_INT (out)

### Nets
+3V3: C56.2 C59.2 C83.1 CN15.24(VDD) CN15.25(VCI) R80.2 R84.2 R86.1 R114.2 R123.2 R137.1 SB8.1 SB9.2 SB10.1 U10.8(VDD) U13.8(VCC) U19.6(VCC) U19.14(Vio)
+5V: R136.1
GND: C56.1 C59.1 C83.2 CN15.26(GND) CN15.27(GND) JP14.2(NO) L2.1 R79.2 R94.1 R113.2 R126.2 U10.4(GND) U10.5(A2) U10.6(A1) U13.2(E1) U13.3(E2) U13.4(VSS) U19.10(GND)
A0: CN15.2(RS)
D0: CN15.6(PD1)
D1: CN15.7(PD2)
D2: CN15.8(PD3)
D3: CN15.9(PD4)
D4: CN15.10(PD5)
D5: CN15.11(PD6)
D6: CN15.12(PD7)
D7: CN15.13(PD8)
D8: CN15.14(PD10)
D9: CN15.15(PD11)
D10: CN15.16(PD12)
D11: CN15.17(PD13)
D12: CN15.18(PD14)
D13: CN15.19(PD15)
D14: CN15.20(PD16)
D15: CN15.21(PD17)
PA12: R99.1 ; port IO_Expandor_INT
PC7: R95.1 ; port LCD_backlight
PD4: CN15.4(~{RD}) ; port FSMC_NOE
PD5: CN15.3(~{WR}/SCL) ; port FSMC_NWE
PG12: R85.2 ; port FSMC_NE3
RESET#: CN15.5(~{RESET}) ; port RESET#
NetC93_1: C93.1 C94.1 CN15.28(BL_VDD) L3.2 R98.2
NetC93_2: C93.2 C94.2 CN15.22(BL_GND) L2.2
NetCN11_5: U19.11(IN2) ; port HP_PLUGIN
NetCN15_1: CN15.1(~{CS}) R84.1 R85.1
NetCN15_23: CN15.23(BL_Control) R95.2 R98.1
NetCN15_31: CN15.31(XL) U19.16(X-)
NetCN15_32: CN15.32(XR) U19.13(X+)
NetCN15_33: CN15.33(YD) U19.1(Y-)
NetCN15_34: CN15.34(YU) U19.15(Y+)
NetJP11_2: R78.1 ; port TemperatureSensor_INT
NetJP14_1: JP14.1(COMMON) R86.2 U13.7(~{WC})
NetL3_1: L3.1 R136.2 R137.2
NetR72_1: U10.1(SDA) U13.5(SDA) U19.5(SDAT) ; port I2C2_SDA
NetR77_1: U10.2(SCL) U13.6(SCL) U19.4(SCLK) ; port I2C2_SCK
NetR78_2: R78.2 R80.1 U10.3(~{OS}/INT)
NetR79_1: R79.1 SB8.2 U10.7(A0)
NetR94_2: R94.2 SB10.2 U13.1(E0)
NetR99_2: R99.2 R114.1 U19.2(INT)
NetR113_1: R113.1 SB9.1 U19.3(A0/Data_Out)
NetR123_1: R123.1 U19.7(Data_in)
NetR126_1: R126.1 U19.9(IN1)

Not connected (* = marked no-connect by the designer): CN15 29(SDO) 30(SDI); U19 8(IN0) 12(IN3)

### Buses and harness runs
bus A[0..20] = port A[0..20]
bus D[0..15] = port D[0..15]

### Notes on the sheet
- (near R85) PD5
- (near R85) PG12
- (near R85) PD4
- (near R99) PA12
- PC7
- 0x88 when SB close
- I2C device address:    0x82 when SB open by default
- (near SB10) 0xA2 when SB close
- (near SB10) I2C device address:    0xA0 when SB open by default
- PB10
- PB11
- (near SB8) 0x92 when SB close
- (near SB8) I2C device address:    0x90 when SB open by default
- PB12
- STM32100E-EVAL LCD,EEPROM &TSensor
- MB901
- 4
- 13

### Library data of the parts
C56 = cap: Capacitor; Value: 100pF
C59 C83 = CAP: Capacitor
C93 = Cap: Capacitor; Value: 10nF
C94 = Cap Pol1: Polarized Capacitor (Radial)
CN15 = 3.2LCD_connector
JP14 = JP2
L2 L3 = Inductor: Value: 100uH
R78-R80 R84 R85 R94 R95 R98 R99 R113 R114 R123 R126 R136 R137 = Res1: Resistor; Value: 1K
R86 = res1: Resistor; Value: 1K
SB8-SB10 = Circuit Breaker
U10 = STLM75DW2F
U13 = M24C64-WMN6
U19 = STMPE811

## Sheet MCU.SchDoc
size A3; Revision: B.1(PCB.SCH)
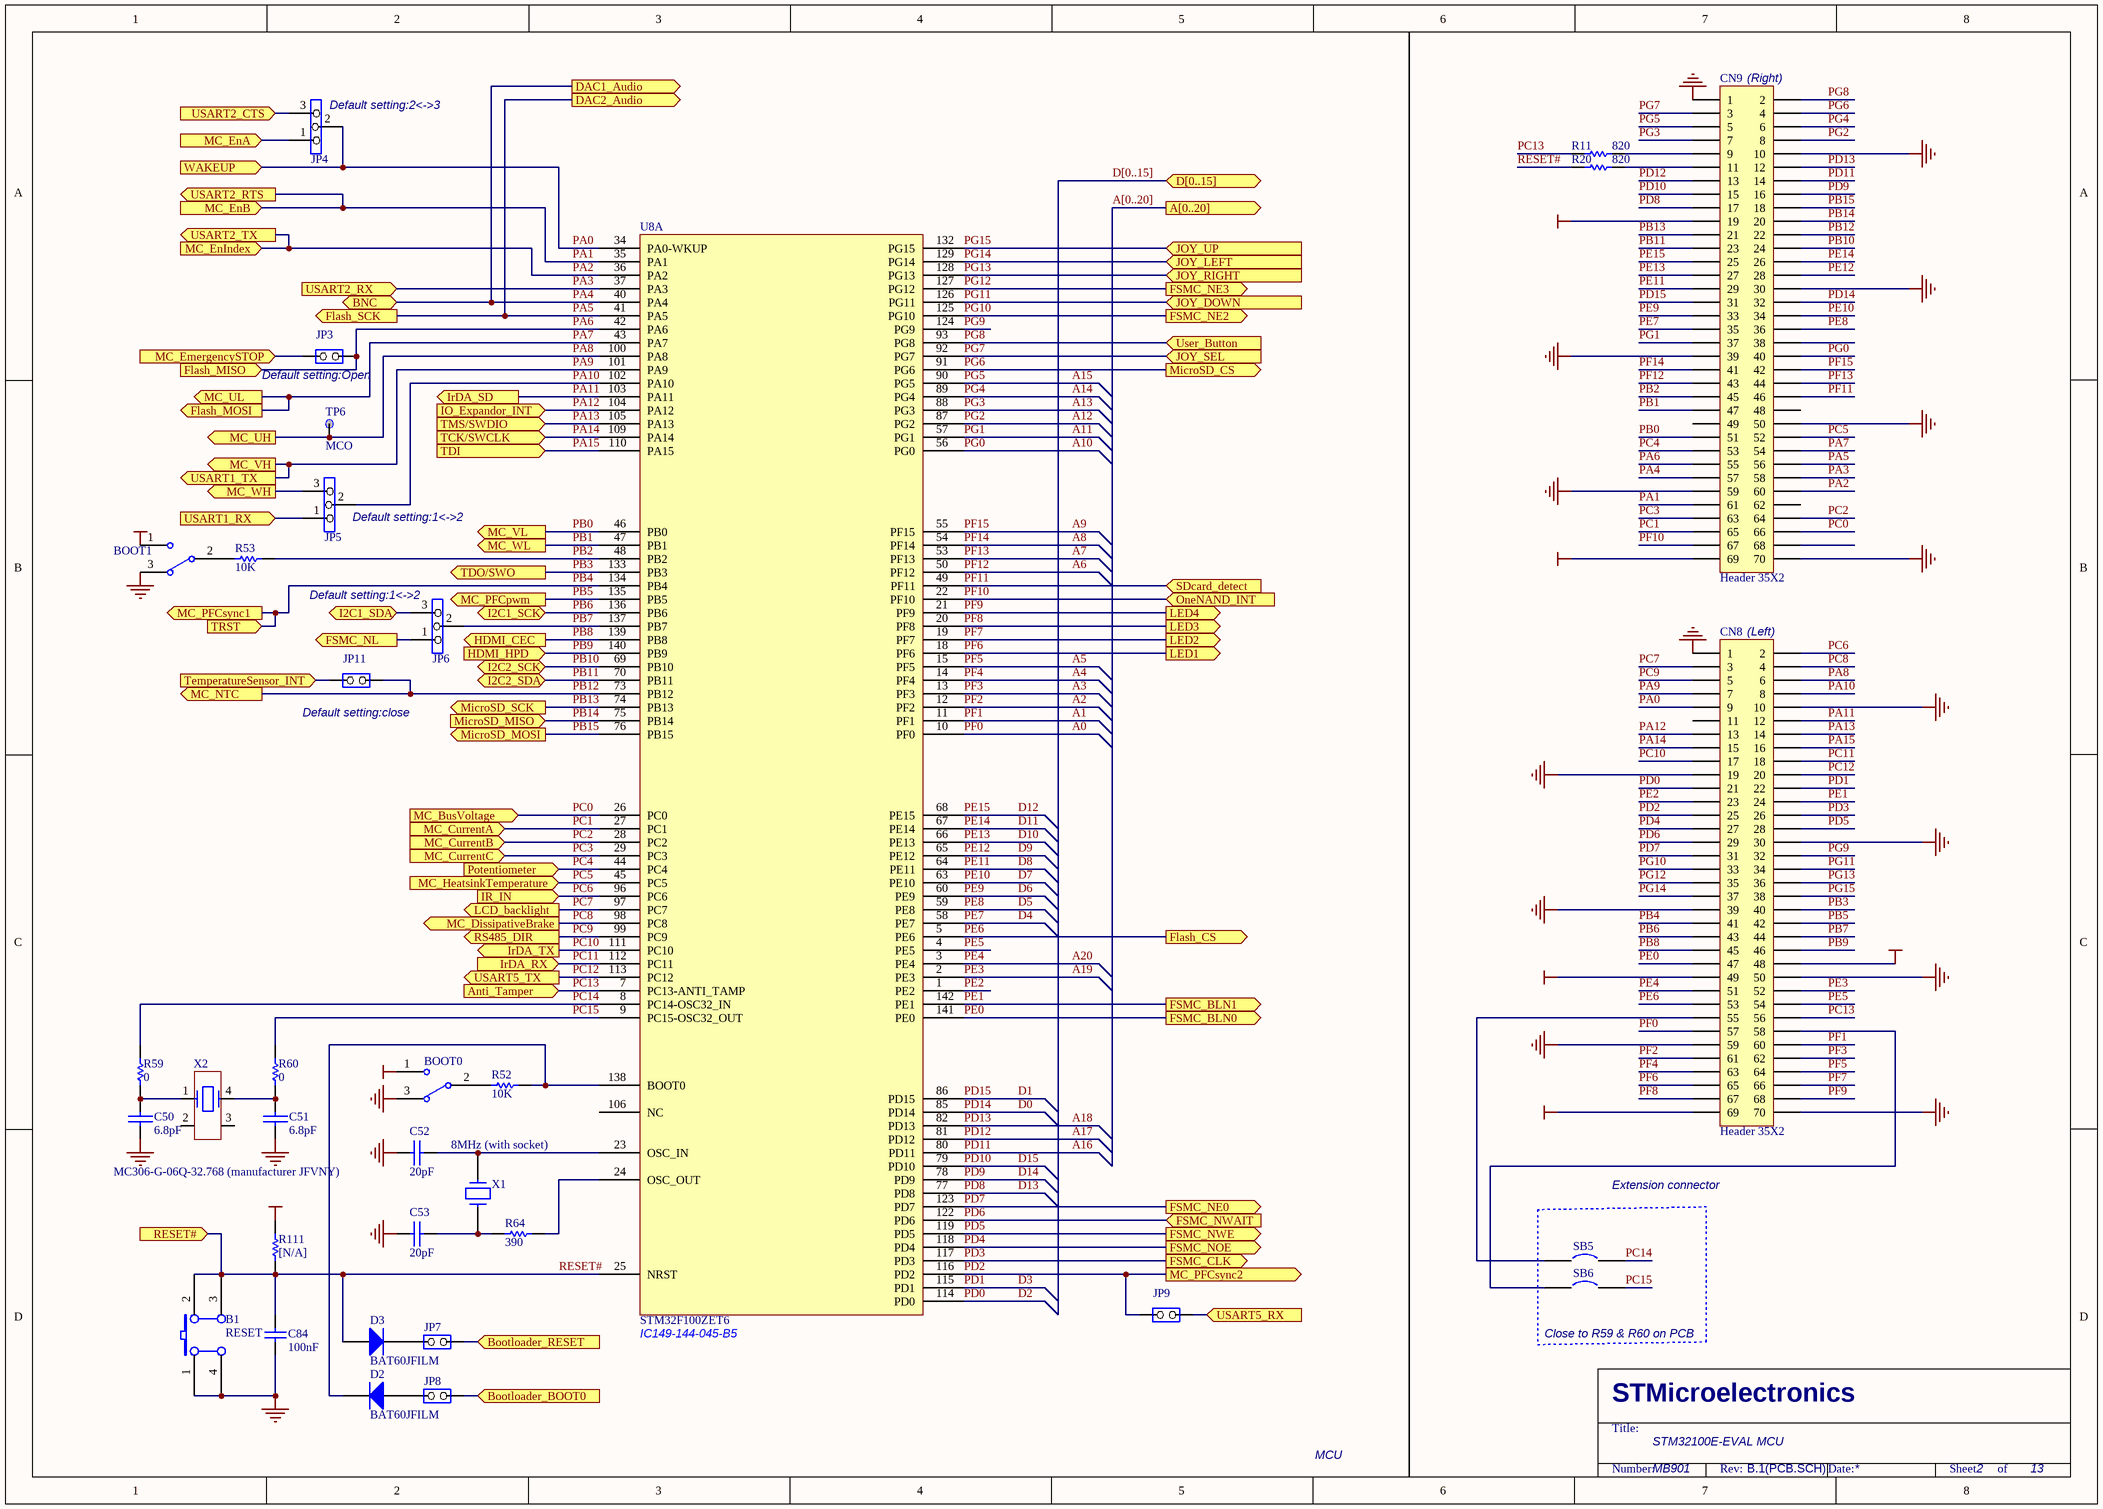
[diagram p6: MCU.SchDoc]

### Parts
B1  RESET  [PB10]
BOOT0  (no value)  [SIP3]
BOOT1  (no value)  [SIP3]
C50  6.8pF  [0603C]
C51  6.8pF  [0603C]
C52  20pF  [0603C]
C53  20pF  [0603C]
C84  100nF  [0402C]
CN8  Header 35X2
CN9  Header 35X2
D2  BAT60JFILM  [SOD-323]
D3  BAT60JFILM  [SOD-323]
JP3  (no value)  [SIP2]
JP4  (no value)  [SIP3]
JP5  (no value)  [SIP3]
JP6  (no value)  [SIP3]
JP7  (no value)  [SIP2]
JP8  (no value)  [SIP2]
JP9  (no value)  [SIP2]
JP11  (no value)  [SIP2]
R11  820  [0603R]
R20  820  [0603R]
R52  10K  [0402R]
R53  10K  [0402R]
R59  0  [0603R]
R60  0  [0603R]
R64  390  [0603R]
R111  [N/A]  [0603R]
SB5  (no value)  [JP2_SMD]
SB6  (no value)  [JP2_SMD]
TP6  MCO  [TP]
U8  STM32F100ZET6  (part A of 2)
X1  8MHz (with socket)  [XTAL_socket]
X2  MC306-G-06Q-32.768 (manufacturer JFVNY)  [SM8]

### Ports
A[0..20] (out), Anti_Tamper (in), BNC (bidir), Bootloader_BOOT0 (in), Bootloader_RESET (in), D[0..15] (bidir), DAC1_Audio (out), DAC2_Audio (out), Flash_CS (out), Flash_MISO (in), Flash_MOSI (out), Flash_SCK (out), FSMC_BLN0 (out), FSMC_BLN1 (out), FSMC_CLK (out), FSMC_NE0 (out), FSMC_NE2 (out), FSMC_NE3 (out), FSMC_NL (out), FSMC_NOE (out), FSMC_NWAIT (in), FSMC_NWE (out), HDMI_CEC (out), HDMI_HPD (in), I2C1_SCK (bidir), I2C1_SDA (bidir), I2C2_SCK (bidir), I2C2_SDA (bidir), IO_Expandor_INT (in), IR_IN (in), IrDA_RX (in), IrDA_SD (out), IrDA_TX (out), JOY_DOWN (in), JOY_LEFT (in), JOY_RIGHT (in), JOY_SEL (in), JOY_UP (in), LCD_backlight (out), LED1 (out), LED2 (out), LED3 (out), LED4 (out), MC_BusVoltage (in), MC_CurrentA (in), MC_CurrentB (in), MC_CurrentC (in), MC_DissipativeBrake (out), MC_EmergencySTOP (in), MC_EnA (in), MC_EnB (in), MC_EnIndex (in), MC_HeatsinkTemperature (in), MC_NTC (out), MC_PFCpwm (out), MC_PFCsync1 (out), MC_PFCsync2 (out), MC_UH (out), MC_UL (out), MC_VH (out), MC_VL (out), MC_WH (out), MC_WL (out), MicroSD_CS (out), MicroSD_MISO (in), MicroSD_MOSI (out), MicroSD_SCK (out), OneNAND_INT (in), Potentiometer (in), RESET# (in), RS485_DIR (out), SDcard_detect (in), TCK/SWCLK (in), TDI (in), TDO/SWO (out), TemperatureSensor_INT (in), TMS/SWDIO (in), TRST (in), USART1_RX (in), USART1_TX (out), USART2_CTS (in), USART2_RTS (out), USART2_RX (in), USART2_TX (out), USART5_RX (in), USART5_TX (out), User_Button (in), WAKEUP (in)

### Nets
+3V3: BOOT0.1 BOOT1.1 CN8.48 CN8.69 CN9.69 R111.2
D5V: CN8.49 CN9.19
GND: B1.1(A0) B1.4(A1) BOOT0.3 BOOT1.3 C50.2 C51.2 C52.2 C53.2 C84.1 CN8.1 CN8.10 CN8.19 CN8.30 CN8.39 CN8.50 CN8.59 CN8.70 CN9.1 CN9.10 CN9.30 CN9.39 CN9.50 CN9.59 CN9.70
A0: CN8.57 U8.10(PF0)  [also labelled PF0]
A1: CN8.60 U8.11(PF1)  [also labelled PF1]
A2: CN8.61 U8.12(PF2)  [also labelled PF2]
A3: CN8.62 U8.13(PF3)  [also labelled PF3]
A4: CN8.63 U8.14(PF4)  [also labelled PF4]
A5: CN8.64 U8.15(PF5)  [also labelled PF5]
A6: CN9.43 U8.50(PF12)  [also labelled PF12]
A7: CN9.44 U8.53(PF13)  [also labelled PF13]
A8: CN9.41 U8.54(PF14)  [also labelled PF14]
A9: CN9.42 U8.55(PF15)  [also labelled PF15]
A10: CN9.40 U8.56(PG0)  [also labelled PG0]
A11: CN9.37 U8.57(PG1)  [also labelled PG1]
A12: CN9.8 U8.87(PG2)  [also labelled PG2]
A13: CN9.7 U8.88(PG3)  [also labelled PG3]
A14: CN9.6 U8.89(PG4)  [also labelled PG4]
A15: CN9.5 U8.90(PG5)  [also labelled PG5]
A16: CN9.14 U8.80(PD11)  [also labelled PD11]
A17: CN9.13 U8.81(PD12)  [also labelled PD12]
A18: CN9.12 U8.82(PD13)  [also labelled PD13]
A19: CN8.52 U8.2(PE3)  [also labelled PE3]
A20: CN8.51 U8.3(PE4)  [also labelled PE4]
D0: CN9.32 U8.85(PD14)  [also labelled PD14]
D1: CN9.31 U8.86(PD15)  [also labelled PD15]
D2: CN8.21 U8.114(PD0)  [also labelled PD0]
D3: CN8.22 U8.115(PD1)  [also labelled PD1]
D4: CN9.35 U8.58(PE7)  [also labelled PE7]
D5: CN9.36 U8.59(PE8)  [also labelled PE8]
D6: CN9.33 U8.60(PE9)  [also labelled PE9]
D7: CN9.34 U8.63(PE10)  [also labelled PE10]
D8: CN9.29 U8.64(PE11)  [also labelled PE11]
D9: CN9.28 U8.65(PE12)  [also labelled PE12]
D10: CN9.27 U8.66(PE13)  [also labelled PE13]
D11: CN9.26 U8.67(PE14)  [also labelled PE14]
D12: CN9.25 U8.68(PE15)  [also labelled PE15]
D13: CN9.17 U8.77(PD8)  [also labelled PD8]
D14: CN9.16 U8.78(PD9)  [also labelled PD9]
D15: CN9.15 U8.79(PD10)  [also labelled PD10]
PA0: CN8.9 JP4.2 U8.34(PA0-WKUP) ; port WAKEUP
PA1: CN9.61 U8.35(PA1) ; port USART2_RTS, port MC_EnB
PA2: CN9.60 U8.36(PA2) ; port USART2_TX, port MC_EnIndex
PA3: CN9.58 U8.37(PA3) ; port USART2_RX
PA4: CN9.57 U8.40(PA4) ; port BNC, port DAC1_Audio
PA5: CN9.56 U8.41(PA5) ; port Flash_SCK, port DAC2_Audio
PA6: CN9.55 JP3.1(COMMON) U8.42(PA6) ; port Flash_MISO
PA7: CN9.54 U8.43(PA7) ; port MC_UL, port Flash_MOSI
PA8: CN8.6 TP6.1 U8.100(PA8) ; port MC_UH
PA9: CN8.7 U8.101(PA9) ; port USART1_TX, port MC_VH
PA10: CN8.8 JP5.2 U8.102(PA10)
PA11: CN8.12 U8.103(PA11) ; port IrDA_SD
PA12: CN8.13 U8.104(PA12) ; port IO_Expandor_INT
PA13: CN8.14 U8.105(PA13) ; port TMS/SWDIO
PA14: CN8.15 U8.109(PA14) ; port TCK/SWCLK
PA15: CN8.16 U8.110(PA15) ; port TDI
PB0: CN9.51 U8.46(PB0) ; port MC_VL
PB1: CN9.47 U8.47(PB1) ; port MC_WL
PB2: CN9.45 R53.1 U8.48(PB2)
PB3: CN8.40 U8.133(PB3) ; port TDO/SWO
PB4: CN8.41 U8.134(PB4) ; port TRST, port MC_PFCsync1
PB5: CN8.42 U8.135(PB5) ; port MC_PFCpwm
PB6: CN8.43 U8.136(PB6) ; port I2C1_SCK
PB7: CN8.44 JP6.2 U8.137(PB7)
PB8: CN8.45 U8.139(PB8) ; port HDMI_CEC
PB9: CN8.46 U8.140(PB9) ; port HDMI_HPD
PB10: CN9.24 U8.69(PB10) ; port I2C2_SCK
PB11: CN9.23 U8.70(PB11) ; port I2C2_SDA
PB12: CN9.22 JP11.1(COMMON) U8.73(PB12) ; port MC_NTC
PB13: CN9.21 U8.74(PB13) ; port MicroSD_SCK
PB14: CN9.20 U8.75(PB14) ; port MicroSD_MISO
PB15: CN9.18 U8.76(PB15) ; port MicroSD_MOSI
PC0: CN9.66 U8.26(PC0) ; port MC_BusVoltage
PC1: CN9.65 U8.27(PC1) ; port MC_CurrentA
PC2: CN9.64 U8.28(PC2) ; port MC_CurrentB
PC3: CN9.63 U8.29(PC3) ; port MC_CurrentC
PC4: CN9.53 U8.44(PC4) ; port Potentiometer
PC5: CN9.52 U8.45(PC5) ; port MC_HeatsinkTemperature
PC6: CN8.2 U8.96(PC6) ; port IR_IN
PC7: CN8.3 U8.97(PC7) ; port LCD_backlight
PC8: CN8.4 U8.98(PC8) ; port MC_DissipativeBrake
PC9: CN8.5 U8.99(PC9) ; port RS485_DIR
PC10: CN8.17 U8.111(PC10) ; port IrDA_TX
PC11: CN8.18 U8.112(PC11) ; port IrDA_RX
PC12: CN8.20 U8.113(PC12) ; port USART5_TX
PC13: CN8.56 R11.1 U8.7(PC13-ANTI_TAMP) ; port Anti_Tamper
PC14: R59.2 SB5.2 U8.8(PC14-OSC32_IN)
PC15: R60.2 SB6.2 U8.9(PC15-OSC32_OUT)
PD2: CN8.25 JP9.2(NO) U8.116(PD2) ; port MC_PFCsync2
PD3: CN8.26 U8.117(PD3) ; port FSMC_CLK
PD4: CN8.27 U8.118(PD4) ; port FSMC_NOE
PD5: CN8.28 U8.119(PD5) ; port FSMC_NWE
PD6: CN8.29 U8.122(PD6) ; port FSMC_NWAIT
PD7: CN8.31 U8.123(PD7) ; port FSMC_NE0
PE0: CN8.47 U8.141(PE0) ; port FSMC_BLN0
PE1: CN8.24 U8.142(PE1) ; port FSMC_BLN1
PE2: CN8.23 U8.1(PE2)
PE5: CN8.54 U8.4(PE5)
PE6: CN8.53 U8.5(PE6) ; port Flash_CS
PF6: CN8.65 U8.18(PF6) ; port LED1
PF7: CN8.66 U8.19(PF7) ; port LED2
PF8: CN8.67 U8.20(PF8) ; port LED3
PF9: CN8.68 U8.21(PF9) ; port LED4
PF10: CN9.67 U8.22(PF10) ; port OneNAND_INT
PF11: CN9.46 U8.49(PF11) ; port SDcard_detect
PG6: CN9.4 U8.91(PG6) ; port MicroSD_CS
PG7: CN9.3 U8.92(PG7) ; port JOY_SEL
PG8: CN9.2 U8.93(PG8) ; port User_Button
PG9: CN8.32 U8.124(PG9)
PG10: CN8.33 U8.125(PG10) ; port FSMC_NE2
PG11: CN8.34 U8.126(PG11) ; port JOY_DOWN
PG12: CN8.35 U8.127(PG12) ; port FSMC_NE3
PG13: CN8.36 U8.128(PG13) ; port JOY_RIGHT
PG14: CN8.37 U8.129(PG14) ; port JOY_LEFT
PG15: CN8.38 U8.132(PG15) ; port JOY_UP
RESET#: B1.2(B0) B1.3(B1) C84.2 D3.1(A) R20.2 R111.1 U8.25(NRST) ; port RESET#
NetBOOT0_2: BOOT0.2 R52.2
NetBOOT1_2: BOOT1.2 R53.2
NetC13_2: JP4.1 ; port MC_EnA
NetC50_1: C50.1 R59.1 X2.1
NetC51_1: C51.1 R60.1 X2.4
NetC52_1: C52.1 U8.23(OSC_IN) X1.2
NetC53_1: C53.1 R64.2 X1.1
NetCN1_11: JP5.3 ; port MC_WH
NetCN8_55: CN8.55 SB5.1
NetCN8_58: CN8.58 SB6.1
NetCN9_9: CN9.9 R11.2
NetCN9_11: CN9.11 R20.1
NetD2_1: D2.1(A) JP8.1(COMMON)
NetD2_2: D2.2(K) R52.1 U8.138(BOOT0)
NetD3_2: D3.2(K) JP7.1(COMMON)
NetJP3_2: JP3.2(NO) ; port MC_EmergencySTOP
NetJP4_3: JP4.3 ; port USART2_CTS
NetJP5_1: JP5.1 ; port USART1_RX
NetJP6_1: JP6.1 ; port FSMC_NL
NetJP6_3: JP6.3 ; port I2C1_SDA
NetJP7_2: JP7.2(NO) ; port Bootloader_RESET
NetJP8_2: JP8.2(NO) ; port Bootloader_BOOT0
NetJP9_1: JP9.1(COMMON) ; port USART5_RX
NetJP11_2: JP11.2(NO) ; port TemperatureSensor_INT
NetR64_1: R64.1 U8.24(OSC_OUT)

Not connected (* = marked no-connect by the designer): CN8 11; CN9 38 48 49 62 68; U8 106(NC); X2 2 3

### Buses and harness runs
bus A[0..20] = port A[0..20]
bus D[0..15] = port D[0..15]

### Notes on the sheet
- (near JP4) Default setting:2<->3
- (near CN9) (Right)
- (near JP3) Default setting:Open
- (near JP5) Default setting:1<->2
- (near JP6) Default setting:1<->2
- (near CN8) (Left)
- (near JP11) Default setting:close
- Extension connector
- (near U8) IC149-144-045-B5
- (near SB6) Close to R59 & R60 on PCB
- MCU
- STM32100E-EVAL MCU
- MB901
- 2
- 13

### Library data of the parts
B1 = SW PUSHBUTTON: SE PUSHBUTTON
BOOT0 BOOT1 = SW-SPDT: SPDT Subminiature Toggle Switch, Right Angle Mounting, Vertical Actuation; Revision 1: Jul-2002: Re-released for DXP Platform.; Revision 2: 17-Dec-2003: Schematic revised, PCB Footprint replaced.
C50-C53 = CAP: Capacitor
C84 = CAP: Capacitor; Value: 100pF
CN8 CN9 = Header35X2
D2 D3 = Diode: Default Diode; Code - JEDEC: DO-214-AB
JP3 JP7-JP9 JP11 = JP2
JP4-JP6 = Jumper3
R11 R20 R59 R60 R64 = Res1: Resistor; Value: 1K
R52 R53 R111 = res1: Resistor; Value: 1K
SB5 SB6 = Circuit Breaker
TP6 = TP
U8 = BigPiranha_new
X1 = CRYSTAL
X2 = MC306

## Sheet MicroSD&SPIFlash.SchDoc
size A4; Revision: B.1(PCB.SCH)
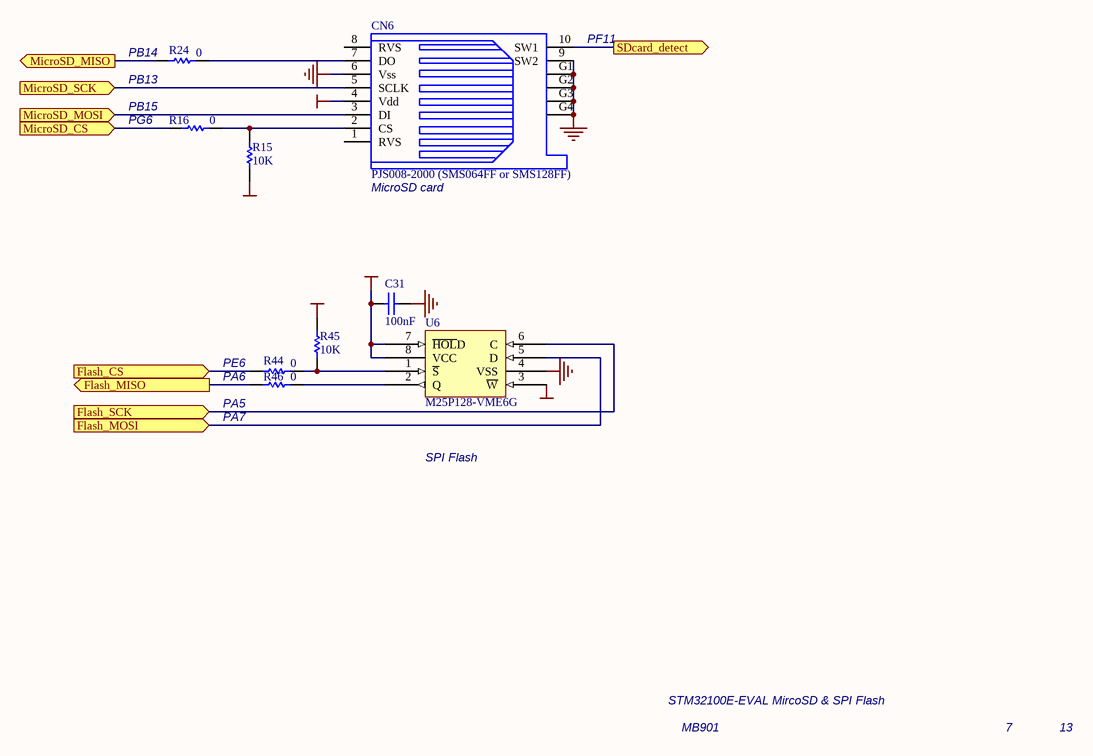
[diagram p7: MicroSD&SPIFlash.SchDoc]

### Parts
C31  100nF  [0402C]
CN6  PJS008-2000 (SMS064FF or SMS128FF)  [MSD(PJS008)]
R15  10K  [0402R]
R16  0  [0603R]
R24  0  [0603R]
R44  0  [0603R]
R45  10K  [0402R]
R46  0  [0603R]
U6  M25P128-VME6G  [VDFPN8(8*6)]

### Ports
Flash_CS (in), Flash_MISO (out), Flash_MOSI (in), Flash_SCK (in), MicroSD_CS (in), MicroSD_MISO (out), MicroSD_MOSI (in), MicroSD_SCK (in), SDcard_detect (out)

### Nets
+3V3: C31.2 CN6.4(Vdd) R15.2 R45.2 U6.3(~{W}) U6.7(~{HOL}D) U6.8(VCC)
GND: C31.1 CN6.6(Vss) CN6.9(SW2) CN6.G1 CN6.G2 CN6.G3 CN6.G4 U6.4(VSS)
PA5: U6.6(C) ; port Flash_SCK
PA6: R46.1 ; port Flash_MISO
PA7: U6.5(D) ; port Flash_MOSI
PB13: CN6.5(SCLK) ; port MicroSD_SCK
PB14: R24.2 ; port MicroSD_MISO
PB15: CN6.3(DI) ; port MicroSD_MOSI
PE6: R44.2 ; port Flash_CS
PF11: CN6.10(SW1) ; port SDcard_detect
PG6: R16.1 ; port MicroSD_CS
NetCN6_2: CN6.2(CS) R15.1 R16.2
NetCN6_7: CN6.7(DO) R24.1
NetR44_1: R44.1 R45.1 U6.1(~{S})
NetR46_2: R46.2 U6.2(Q)

Not connected (* = marked no-connect by the designer): CN6 1(RVS) 8(RVS)

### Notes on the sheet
- (near CN6) PF11
- (near R24) PB13
- PB15
- (near R24) PB14
- (near R16) PG6
- (near CN6) MicroSD card
- PE6
- PA6
- PA5
- PA7
- SPI Flash
- STM32100E-EVAL MircoSD & SPI Flash
- MB901
- 7
- 13

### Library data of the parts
C31 = CAP: Capacitor
CN6 = SMS016AFA5E
R15 R16 R24 R44-R46 = Res1: Resistor; Value: 1K
U6 = M25P64-VME6G

## Sheet MotorCtrl.SchDoc
size A4; Revision: B.1(PCB.SCH)
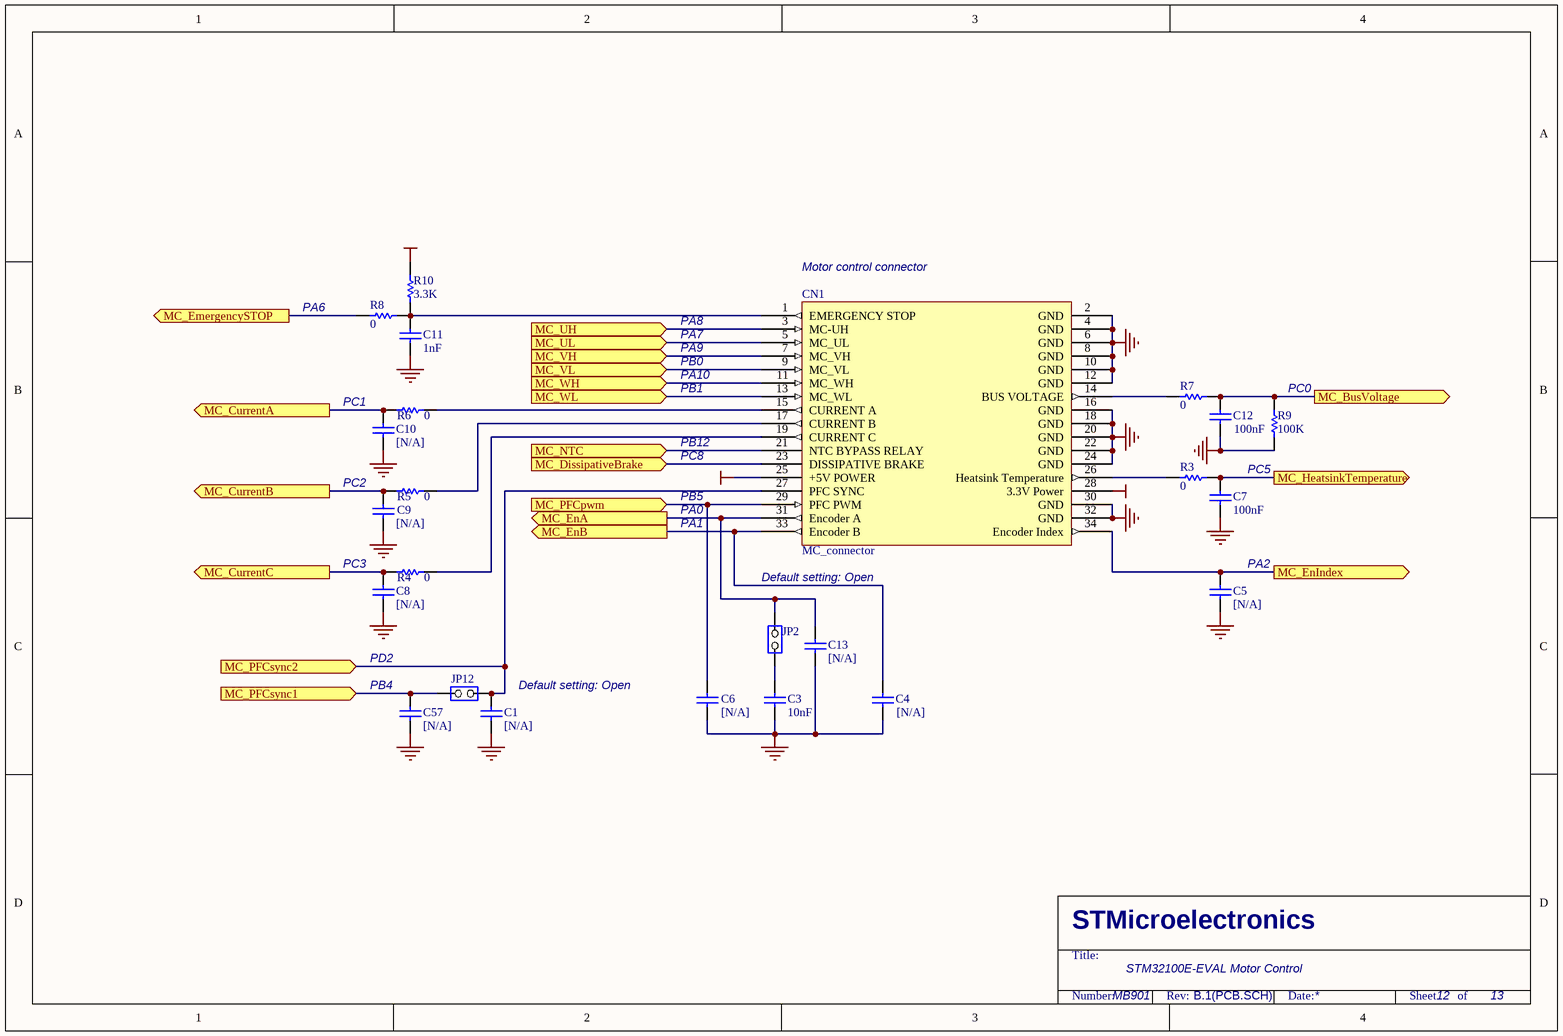
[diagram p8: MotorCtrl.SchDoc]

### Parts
C1  [N/A]  [0603C]
C3  10nF  [0603C]
C4  [N/A]  [0603C]
C5  [N/A]  [0603C]
C6  [N/A]  [0603C]
C7  100nF  [0402C]
C8  [N/A]  [0603C]
C9  [N/A]  [0603C]
C10  [N/A]  [0603C]
C11  1nF  [0603C]
C12  100nF  [0402C]
C13  [N/A]  [0603C]
C57  [N/A]  [0603C]
CN1  MC_connector  [IDC34S]
JP2  (no value)  [SIP2]
JP12  (no value)  [SIP2]
R3  0  [0603R]
R4  0  [0603R]
R5  0  [0603R]
R6  0  [0603R]
R7  0  [0603R]
R8  0  [0603R]
R9  100K  [0603R]
R10  3.3K  [0603R]

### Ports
MC_BusVoltage (out), MC_CurrentA (out), MC_CurrentB (out), MC_CurrentC (out), MC_DissipativeBrake (in), MC_EmergencySTOP (out), MC_EnA (out), MC_EnB (out), MC_EnIndex (out), MC_HeatsinkTemperature (out), MC_NTC (in), MC_PFCpwm (in), MC_PFCsync1 (in), MC_PFCsync2 (in), MC_UH (in), MC_UL (in), MC_VH (in), MC_VL (in), MC_WH (in), MC_WL (in)

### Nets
+3V3: CN1.28(3.3V_Power) R10.2
+5V: CN1.25(+5V_POWER)
GND: C1.1 C3.1 C4.1 C5.1 C6.1 C7.1 C8.1 C9.1 C10.1 C11.1 C12.1 C13.1 C57.1 CN1.2(GND) CN1.4(GND) CN1.6(GND) CN1.8(GND) CN1.10(GND) CN1.12(GND) CN1.16(GND) CN1.18(GND) CN1.20(GND) CN1.22(GND) CN1.24(GND) CN1.30(GND) CN1.32(GND) R9.1
PA1: C4.2 CN1.33(Encoder_B) ; port MC_EnB
PA2: C5.2 CN1.34(Encoder_Index) ; port MC_EnIndex
PA7: CN1.5(MC_UL) ; port MC_UL
PA8: CN1.3(MC-UH) ; port MC_UH
PA9: CN1.7(MC_VH) ; port MC_VH
PB0: CN1.9(MC_VL) ; port MC_VL
PB1: CN1.13(MC_WL) ; port MC_WL
PB4: C57.2 JP12.2(NO) ; port MC_PFCsync1
PB5: C6.2 CN1.29(PFC_PWM) ; port MC_PFCpwm
PB12: CN1.21(NTC_BYPASS_RELAY) ; port MC_NTC
PC0: C12.2 R7.2 R9.2 ; port MC_BusVoltage
PC1: C10.2 R6.1 ; port MC_CurrentA
PC2: C9.2 R5.1 ; port MC_CurrentB
PC3: C8.2 R4.1 ; port MC_CurrentC
PC5: C7.2 R3.2 ; port MC_HeatsinkTemperature
PC8: CN1.23(DISSIPATIVE_BRAKE) ; port MC_DissipativeBrake
PD2: C1.2 CN1.27(PFC_SYNC) JP12.1(COMMON) ; port MC_PFCsync2
NetC3_2: C3.2 JP2.2(NO)
NetC11_2: C11.2 CN1.1(EMERGENCY_STOP) R8.1 R10.1
NetC13_2: C13.2 CN1.31(Encoder_A) JP2.1(COMMON) ; port MC_EnA
NetCN1_11: CN1.11(MC_WH) ; port MC_WH
NetCN1_14: CN1.14(BUS_VOLTAGE) R7.1
NetCN1_15: CN1.15(CURRENT_A) R6.2
NetCN1_17: CN1.17(CURRENT_B) R5.2
NetCN1_19: CN1.19(CURRENT_C) R4.2
NetCN1_26: CN1.26(Heatsink_Temperature) R3.1
NetJP3_2: R8.2 ; port MC_EmergencySTOP

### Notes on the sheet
- (near R8) PA6
- (near CN1) Motor control connector
- PA8
- PA7
- PA9
- PB0
- PA10
- PC1
- PB1
- PB12
- (near R9) PC0
- PC2
- PC8
- PA0
- PB5
- PC5
- PC3
- PA1
- Default setting: Open
- (near C5) PA2
- (near C57) PB4
- PD2
- (near C1) Default setting: Open
- STM32100E-EVAL Motor Control
- MB901
- 12
- 13

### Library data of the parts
C1 C3-C10 C12 C13 C57 = cap: Capacitor; Value: 100pF
C11 = CAP: Capacitor; Value: 100pF
JP2 JP12 = JP2
R3-R10 = Res1: Resistor; Value: 1K

## Sheet Power.SchDoc
size A4; Revision: B.1(PCB.SCH)
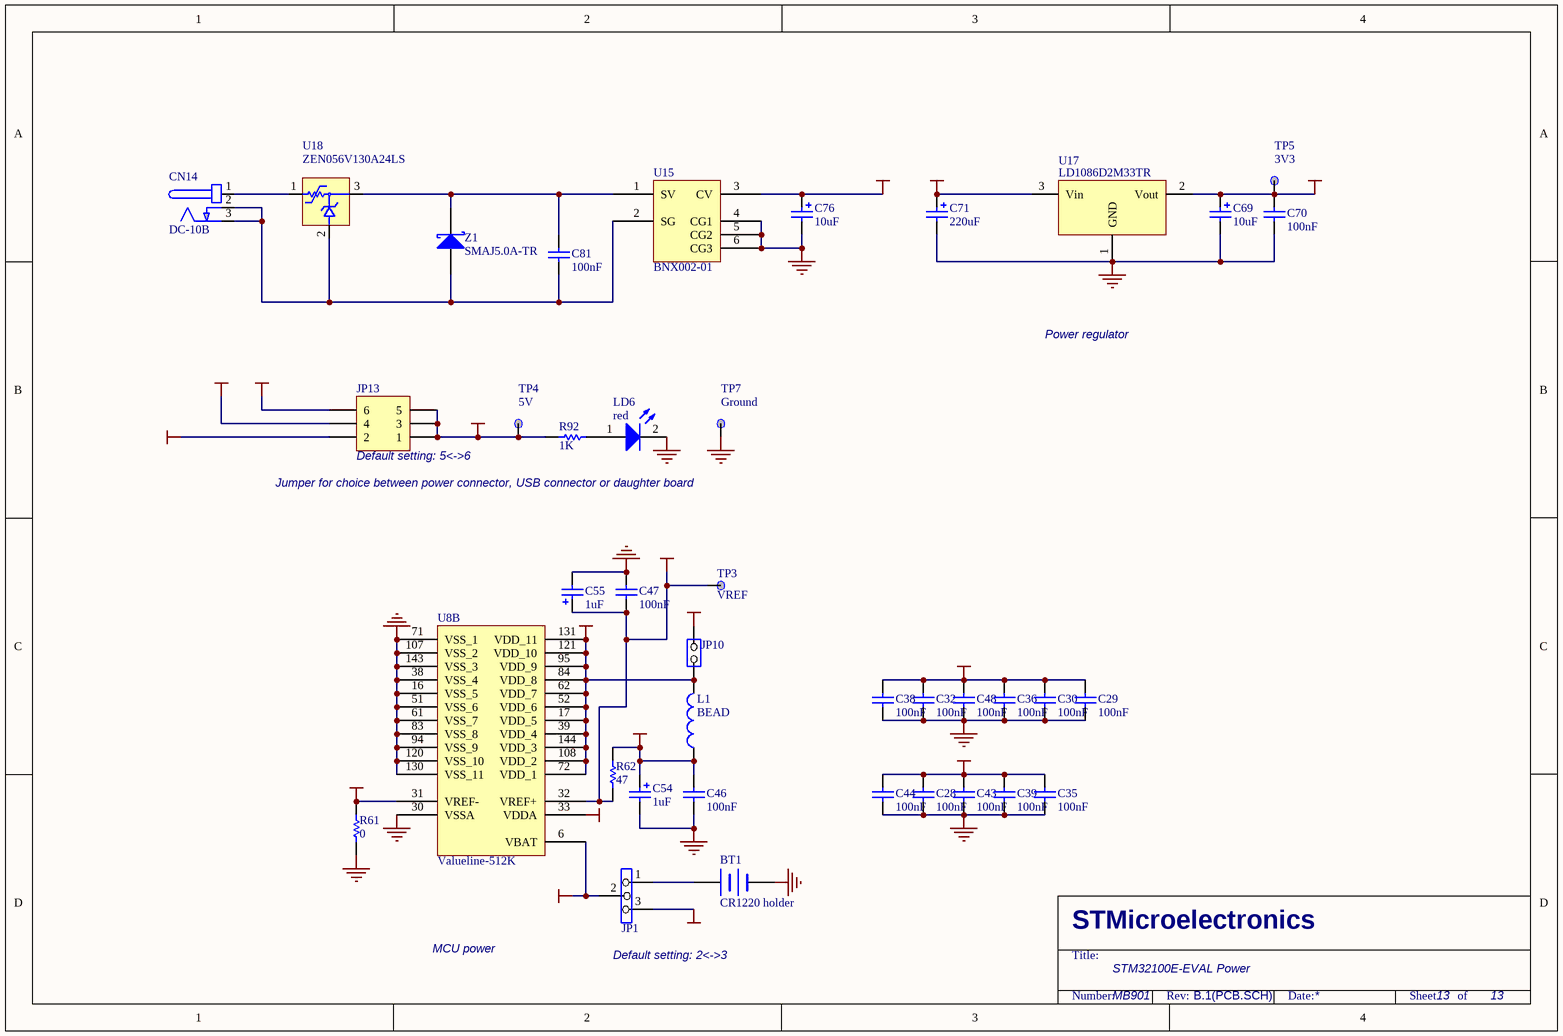
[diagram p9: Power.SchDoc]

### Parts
BT1  CR1220 holder  [LI1220_1]
C28  100nF  [0402C]
C29  100nF  [0402C]
C30  100nF  [0402C]
C32  100nF  [0402C]
C35  100nF  [0402C]
C36  100nF  [0402C]
C38  100nF  [0402C]
C39  100nF  [0402C]
C43  100nF  [0402C]
C44  100nF  [0402C]
C46  100nF  [0402C]
C47  100nF  [0402C]
C48  100nF  [0402C]
C54  1uF  [TAN-A]
C55  1uF  [TAN-A]
C69  10uF  [TAN-A]
C70  100nF  [0402C]
C71  220uF  [C310M]
C76  10uF  [C160M]
C81  100nF  [0402C]
CN14  DC-10B  [DC10B]
JP1  (no value)  [SIP3]
JP10  (no value)  [SIP2]
JP13  (no value)  [2*3P]
L1  BEAD  [0603L]
LD6  red  [0603D]
R61  0  [0603R]
R62  47  [0603R]
R92  1K  [0603R]
TP3  VREF  [TP]
TP4  5V  [TP]
TP5  3V3  [TP]
TP7  Ground  [TP]
U8  Valueline-512K  (part B of 2)
U15  BNX002-01  [BNX001]
U17  LD1086D2M33TR  [D2PAK/A]
U18  ZEN056V130A24LS  [polyzen]
Z1  SMAJ5.0A-TR  [1R1C]

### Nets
+3V3: C69.1 C70.1 JP1.3 JP10.2(NO) TP5.1 U17.2(Vout)
+5V: C71.1 JP13.1 JP13.3 JP13.5 R92.2 TP4.1 U17.3(Vin)
D5V: JP13.4
E5V: C76.1 JP13.6 U15.3(CV)
GND: BT1.2(-) C28.2 C29.2 C30.2 C32.2 C35.2 C36.2 C38.2 C39.2 C43.2 C44.2 C46.1 C47.2 C48.2 C54.2 C55.2 C69.2 C70.2 C71.2 C76.2 LD6.2(K) R61.2 TP7.1 U8.16(VSS_5) U8.30(VSSA) U8.38(VSS_4) U8.51(VSS_6) U8.61(VSS_7) U8.71(VSS_1) U8.83(VSS_8) U8.94(VSS_9) U8.107(VSS_2) U8.120(VSS_10) U8.130(VSS_11) U8.143(VSS_3) U15.4(CG1) U15.5(CG2) U15.6(CG3) U17.1(GND)
U5V_ST_LINK: JP13.2
Vbat: JP1.2 U8.6(VBAT)
VDD: C28.1 C29.1 C30.1 C32.1 C35.1 C36.1 C38.1 C39.1 C43.1 C44.1 C48.1 JP10.1(COMMON) L1.2 U8.17(VDD_5) U8.39(VDD_4) U8.52(VDD_6) U8.62(VDD_7) U8.72(VDD_1) U8.84(VDD_8) U8.95(VDD_9) U8.108(VDD_2) U8.121(VDD_10) U8.131(VDD_11) U8.144(VDD_3)
VDDA: C46.2 C54.1 L1.1 R62.2 U8.33(VDDA)
VREF+: C47.1 C55.1 R62.1 TP3.1 U8.32(VREF+)
VREF-: R61.1 U8.31(VREF-)
NetBT1_1: BT1.1(+) JP1.1
NetC81_1: C81.1 U15.1(SV) U18.3 Z1.2(K)
NetC81_2: C81.2 CN14.2(GND) CN14.3(GND) U15.2(SG) U18.2 Z1.1(A)
NetCN14_1: CN14.1(+) U18.1
NetLD6_1: LD6.1(A) R92.1

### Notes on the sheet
- Power regulator
- Jumper for choice between power connector, USB connector or daughter board
- (near JP13) Default setting: 5<->6
- MCU power
- (near JP1) Default setting: 2<->3
- STM32100E-EVAL Power
- MB901
- 13

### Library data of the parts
BT1 = BATTERY
C28-C30 C32 C35 C36 C38 C39 C43 C44 C48 = CAP: Capacitor
C46 C47 C70 = Cap: Capacitor; Value: 10nF
C54 C55 C71 = Cap Pol1: as C58 on sheet Audio
C69 = Cap Pol1: Polarized Capacitor (Radial)
C76 = Cap Pol1: Polarized Capacitor (Radial); Value: 47uF
C81 = CAP: Capacitor; Value: 100pF
CN14 = PJ202A
JP1 = Jumper3
JP10 = JP2
JP13 = Header 3X2: Header, 3-Pin, Dual row
L1 = Inductor: Value: 100uH
LD6 = LED2: as LD1 on sheet IO_Peripheral
R61 R62 = Res1: Resistor; Value: 1K
R92 = res1: Resistor
TP3-TP5 TP7 = TP
U8 = BigPiranha_new
U15 = BNX002
U17 = VOLTREG1
Z1 = D Schottky: Schottky Diode; Code - JEDEC: DO-214-AA

## Sheet RS232&IrDA.SchDoc
size A4; Revision: B.1(PCB.SCH)
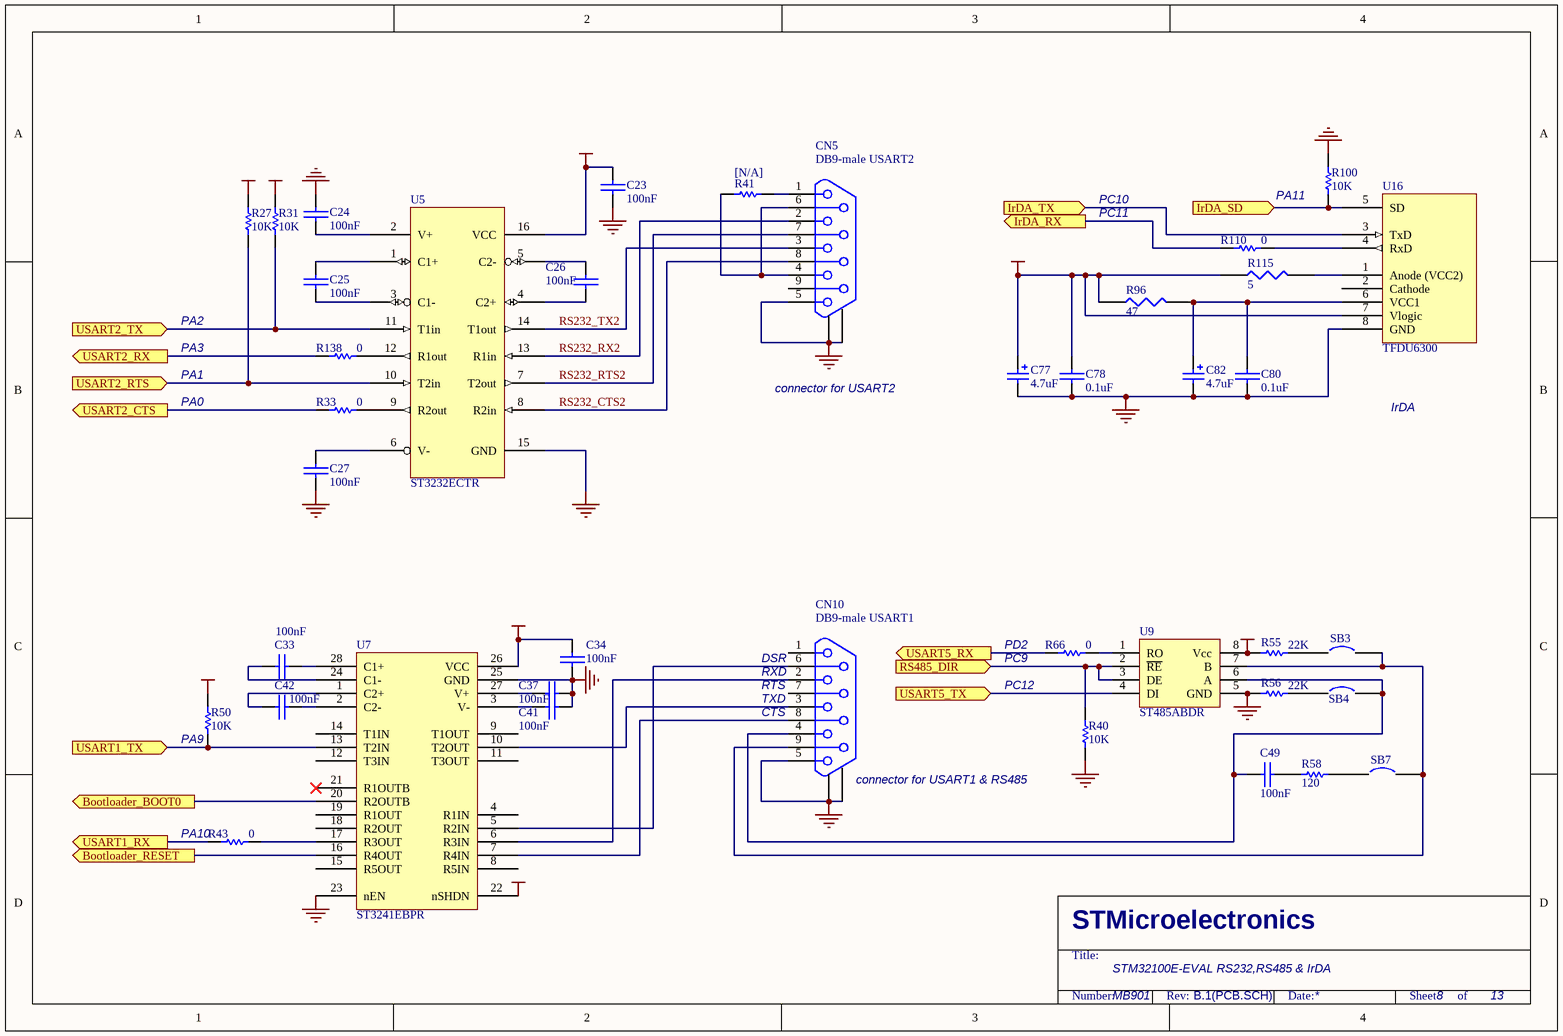
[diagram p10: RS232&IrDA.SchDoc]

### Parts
C23  100nF  [0402C]
C24  100nF  [0402C]
C25  100nF  [0402C]
C26  100nF  [0402C]
C27  100nF  [0402C]
C33  100nF  [0402C]
C34  100nF  [0402C]
C37  100nF  [0402C]
C41  100nF  [0402C]
C42  100nF  [0402C]
C49  100nF  [0402C]
C77  4.7uF  [TAN-A]
C78  0.1uF  [0402C]
C80  0.1uF  [0402C]
C82  4.7uF  [TAN-A]
CN5  DB9-male USART2  [DB9/M]
CN10  DB9-male USART1  [DB9/M]
R27  10K  [0402R]
R31  10K  [0402R]
R33  0  [0603R]
R40  10K  [0402R]
R41  [N/A]  [0603R]
R43  0  [0603R]
R50  10K  [0402R]
R55  22K  [0603R]
R56  22K  [0603R]
R58  120  [0603R]
R66  0  [0603R]
R96  47  [0603R]
R100  10K  [0402R]
R110  0  [0603R]
R115  5  [0603R]
R138  0  [0603R]
SB3  (no value)  [JP2_SMD]
SB4  (no value)  [JP2_SMD]
SB7  (no value)  [JP2_SMD]
U5  ST3232ECTR  [TSSOP16]
U7  ST3241EBPR  [SSOP28]
U9  ST485ABDR  [SO8]
U16  TFDU6300  [IR_VISHAY3]

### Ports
Bootloader_BOOT0 (out), Bootloader_RESET (out), IrDA_RX (out), IrDA_SD (in), IrDA_TX (in), RS485_DIR (in), USART1_RX (out), USART1_TX (in), USART2_CTS (out), USART2_RTS (in), USART2_RX (out), USART2_TX (in), USART5_RX (out), USART5_TX (in)

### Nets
+3V3: C23.1 C34.2 C77.1 C78.1 R27.1 R31.1 R50.1 R96.1 R115.1 U5.16(VCC) U7.22(nSHDN) U7.26(VCC) U16.7(Vlogic)
+5V: R55.2 U9.8(Vcc)
GND: C23.2 C24.1 C27.1 C34.1 C37.2 C41.2 C77.2 C78.2 C80.2 C82.2 CN5.0 CN5.5 CN10.0 CN10.5 R40.1 R56.2 R100.2 U5.15(GND) U7.23(nEN) U7.25(GND) U9.5(GND) U16.8(GND)
PA1: R27.2 U5.10(T2in) ; port USART2_RTS
PA2: R31.2 U5.11(T1in) ; port USART2_TX
PA3: R138.2 ; port USART2_RX
PA9: R50.2 U7.13(T2IN) ; port USART1_TX
PA11: R100.1 U16.5(SD) ; port IrDA_SD
PC9: R40.2 U9.2(~{RE}) U9.3(DE) ; port RS485_DIR
PC10: U16.3(TxD) ; port IrDA_TX
PC11: R110.2 ; port IrDA_RX
PC12: U9.4(DI) ; port USART5_TX
RS232_CTS2: CN5.8 U5.8(R2in)
RS232_RTS2: CN5.7 U5.7(T2out)
RS232_RX2: CN5.2 U5.13(R1in)
RS232_TX2: CN5.3 U5.14(T1out)
NetC24_2: C24.2 U5.2(V+)
NetC25_1: C25.1 U5.1(C1+)
NetC25_2: C25.2 U5.3(C1-)
NetC26_1: C26.1 U5.4(C2+)
NetC26_2: C26.2 U5.5(C2-)
NetC27_2: C27.2 U5.6(V-)
NetC33_1: C33.1 U7.24(C1-)
NetC33_2: C33.2 U7.28(C1+)
NetC37_1: C37.1 U7.27(V+)
NetC41_1: C41.1 U7.3(V-)
NetC42_1: C42.1 U7.1(C2+)
NetC42_2: C42.2 U7.2(C2-)
NetC49_1: C49.1 R58.1
NetC49_2: C49.2 CN10.4 SB4.2 U9.6(A)
NetC80_1: C80.1 C82.1 R96.2 U16.6(VCC1)
NetCN5_1: CN5.1 R41.2
NetCN5_4: CN5.4 CN5.6 R41.1
NetCN10_2: CN10.2 U7.6(R3IN)
NetCN10_3: CN10.3 U7.10(T2OUT)
NetCN10_6: CN10.6 U7.5(R2IN)
NetCN10_8: CN10.8 U7.7(R4IN)
NetCN10_9: CN10.9 SB3.2 SB7.2 U9.7(B)
NetJP4_3: R33.2 ; port USART2_CTS
NetJP5_1: R43.2 ; port USART1_RX
NetJP7_2: U7.16(R4OUT) ; port Bootloader_RESET
NetJP8_2: U7.20(R2OUTB) ; port Bootloader_BOOT0
NetJP9_1: R66.2 ; port USART5_RX
NetR33_1: R33.1 U5.9(R2out)
NetR43_1: R43.1 U7.17(R3OUT)
NetR55_1: R55.1 SB3.1
NetR56_1: R56.1 SB4.1
NetR58_2: R58.2 SB7.1
NetR66_1: R66.1 U9.1(RO)
NetR110_1: R110.1 U16.4(RxD)
NetR115_2: R115.2 U16.1(Anode_(VCC2))
NetR138_1: R138.1 U5.12(R1out)

Not connected (* = marked no-connect by the designer): CN5 9; CN10 1 7; U7 4(R1IN) 8(R5IN) 9(T1OUT) 11(T3OUT) 12(T3IN) 14(T1IN) 15(R5OUT) 18(R2OUT) 19(R1OUT) 21(R1OUTB)*; U16 2(Cathode)

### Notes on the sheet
- PC10
- PC11
- (near R100) PA11
- PA1
- PA2
- PA3
- PA0
- connector for USART2
- IrDA
- (near R66) PD2
- (near CN10) RXD
- (near CN10) RTS
- (near CN10) TXD
- (near CN10) CTS
- (near CN10) DSR
- (near R66) PC9
- PC12
- (near R50) PA9
- (near CN10) connector for USART1 & RS485
- (near R43) PA10
- STM32100E-EVAL RS232,RS485 & IrDA
- MB901
- 8
- 13

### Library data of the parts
C23-C27 C33 C34 C37 C41 C42 C49 C78 C80 = CAP: Capacitor
C77 C82 = Cap Pol1: Polarized Capacitor (Radial); Value: 100pF
CN5 CN10 = DB9
R27 R31 R33 R40 R43 R50 R55 R56 R58 R66 R100 R110 R138 = Res1: Resistor; Value: 1K
R41 = res1: Resistor; Value: 1K
R96 R115 = RES1
SB3 SB4 SB7 = Circuit Breaker
U5 = ST3232: 3.3V/5V Dual RS232 Transceiver w/ Int. Cap.
U7 = ST3241
U16 = TFDU4300

## Sheet SRAM&OneNAND.SchDoc
size A4; Revision: B.1(PCB.SCH)
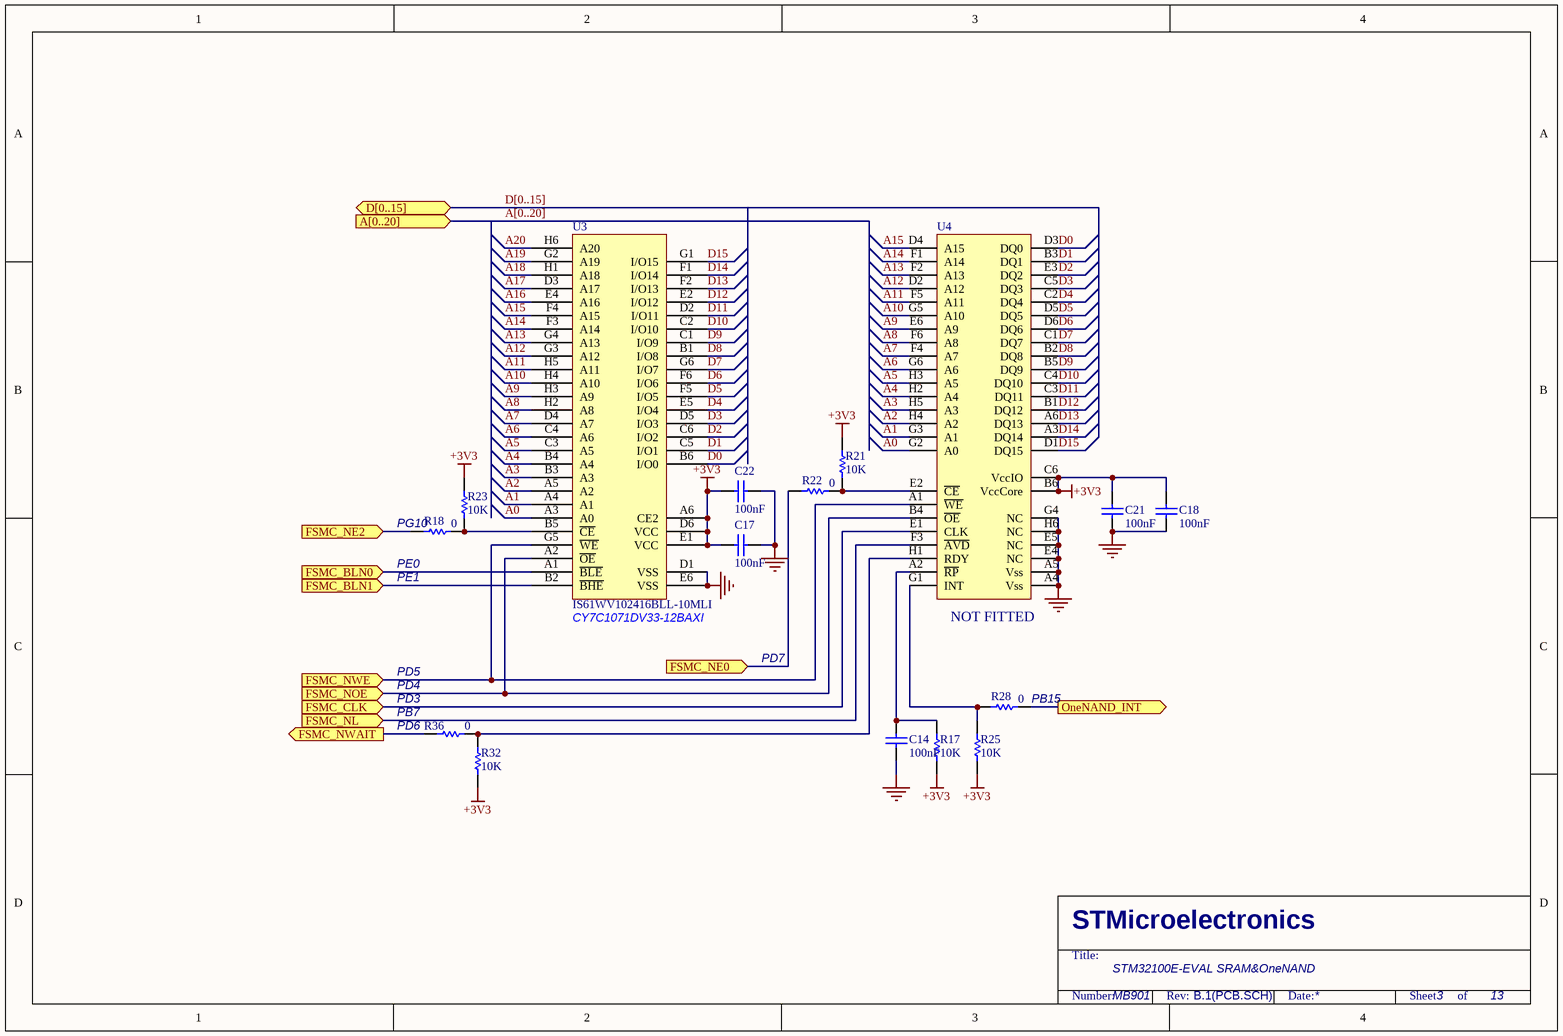
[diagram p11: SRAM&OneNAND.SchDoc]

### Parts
C14  100nF  [0402C]
C17  100nF  [0402C]
C18  100nF  [0402C]
C21  100nF  [0402C]
C22  100nF  [0402C]
R17  10K  [0402R]
R18  0  [0603R]
R21  10K  [0402R]
R22  0  [0603R]
R23  10K  [0402R]
R25  10K  [0402R]
R28  0  [0603R]
R32  10K  [0402R]
R36  0  [0603R]
U3  IS61WV102416BLL-10MLI  [FBGA48(9*11)]
U4  KFG1216U2B-DIB6  [FBGA63(9.5*12)]  (value not drawn)

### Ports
A[0..20] (in), D[0..15] (bidir), FSMC_BLN0 (in), FSMC_BLN1 (in), FSMC_CLK (in), FSMC_NE0 (in), FSMC_NE2 (in), FSMC_NL (in), FSMC_NOE (in), FSMC_NWAIT (out), FSMC_NWE (in), OneNAND_INT (out)

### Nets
+3V3: C17.2 C18.1 C21.1 C22.2 R17.1 R21.2 R23.2 R25.1 R32.1 U3.A6(CE2) U3.D6(VCC) U3.E1(VCC) U4.B6(VccCore) U4.C6(VccIO)
GND: C14.1 C17.1 C18.2 C21.2 C22.1 U3.D1(VSS) U3.E6(VSS) U4.A4(Vss) U4.A5(Vss) U4.E4(NC) U4.E5(NC) U4.G4(NC) U4.H6(NC)
A0: U3.A3(A0) U4.G2(A0)
A1: U3.A4(A1) U4.G3(A1)
A2: U3.A5(A2) U4.H4(A2)
A3: U3.B3(A3) U4.H5(A3)
A4: U3.B4(A4) U4.H2(A4)
A5: U3.C3(A5) U4.H3(A5)
A6: U3.C4(A6) U4.G6(A6)
A7: U3.D4(A7) U4.F4(A7)
A8: U3.H2(A8) U4.F6(A8)
A9: U3.H3(A9) U4.E6(A9)
A10: U3.H4(A10) U4.G5(A10)
A11: U3.H5(A11) U4.F5(A11)
A12: U3.G3(A12) U4.D2(A12)
A13: U3.G4(A13) U4.F2(A13)
A14: U3.F3(A14) U4.F1(A14)
A15: U3.F4(A15) U4.D4(A15)
A16: U3.E4(A16)
A17: U3.D3(A17)
A18: U3.H1(A18)
A19: U3.G2(A19)
A20: U3.H6(A20)
D0: U3.B6(I/O0) U4.D3(DQ0)
D1: U3.C5(I/O1) U4.B3(DQ1)
D2: U3.C6(I/O2) U4.E3(DQ2)
D3: U3.D5(I/O3) U4.C5(DQ3)
D4: U3.E5(I/O4) U4.C2(DQ4)
D5: U3.F5(I/O5) U4.D5(DQ5)
D6: U3.F6(I/O6) U4.D6(DQ6)
D7: U3.G6(I/O7) U4.C1(DQ7)
D8: U3.B1(I/O8) U4.B2(DQ8)
D9: U3.C1(I/O9) U4.B5(DQ9)
D10: U3.C2(I/O10) U4.C4(DQ10)
D11: U3.D2(I/O11) U4.C3(DQ11)
D12: U3.E2(I/O12) U4.B1(DQ12)
D13: U3.F2(I/O13) U4.A6(DQ13)
D14: U3.F1(I/O14) U4.A3(DQ14)
D15: U3.G1(I/O15) U4.D1(DQ15)
PD3: U4.E1(CLK) ; port FSMC_CLK
PD4: U3.A2(~{OE}) U4.B4(~{OE}) ; port FSMC_NOE
PD5: U3.G5(~{WE}) U4.A1(~{WE}) ; port FSMC_NWE
PD6: R36.2 ; port FSMC_NWAIT
PD7: R22.2 ; port FSMC_NE0
PE0: U3.A1(~{BLE}) ; port FSMC_BLN0
PE1: U3.B2(~{BHE}) ; port FSMC_BLN1
PF10: R28.1 ; port OneNAND_INT
PG10: R18.2 ; port FSMC_NE2
NetC14_2: C14.2 R17.2 U4.A2(~{RP})
NetJP6_1: U4.F3(~{AVD}) ; port FSMC_NL
NetR18_1: R18.1 R23.1 U3.B5(~{CE})
NetR21_1: R21.1 R22.1 U4.E2(~{CE})
NetR25_2: R25.2 R28.2 U4.G1(INT)
NetR32_2: R32.2 R36.1 U4.H1(RDY)

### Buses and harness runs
bus A[0..20] = port A[0..20]
bus D[0..15] = port D[0..15]

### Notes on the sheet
- (near R18) PE0
- (near R18) PE1
- (near R18) PG10
- (near U3) CY7C1071DV33-12BAXI
- (near U4) NOT FITTED
- PD5
- (near R36) PD4
- (near R36) PD3
- (near R36) PB7
- PD7
- (near R28) PB15
- (near R36) PD6
- STM32100E-EVAL SRAM&OneNAND
- MB901
- 3
- 13

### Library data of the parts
C14 C17 C18 C21 C22 = cap: Capacitor; Value: 100pF
R17 R18 R21-R23 R25 R28 R32 R36 = Res1: Resistor; Value: 1K
U4 = KFG1216U2A-DIB6

## Sheet ST_LINK.SCHDOC
size A4; Revision: B.1(PCB.SCH)
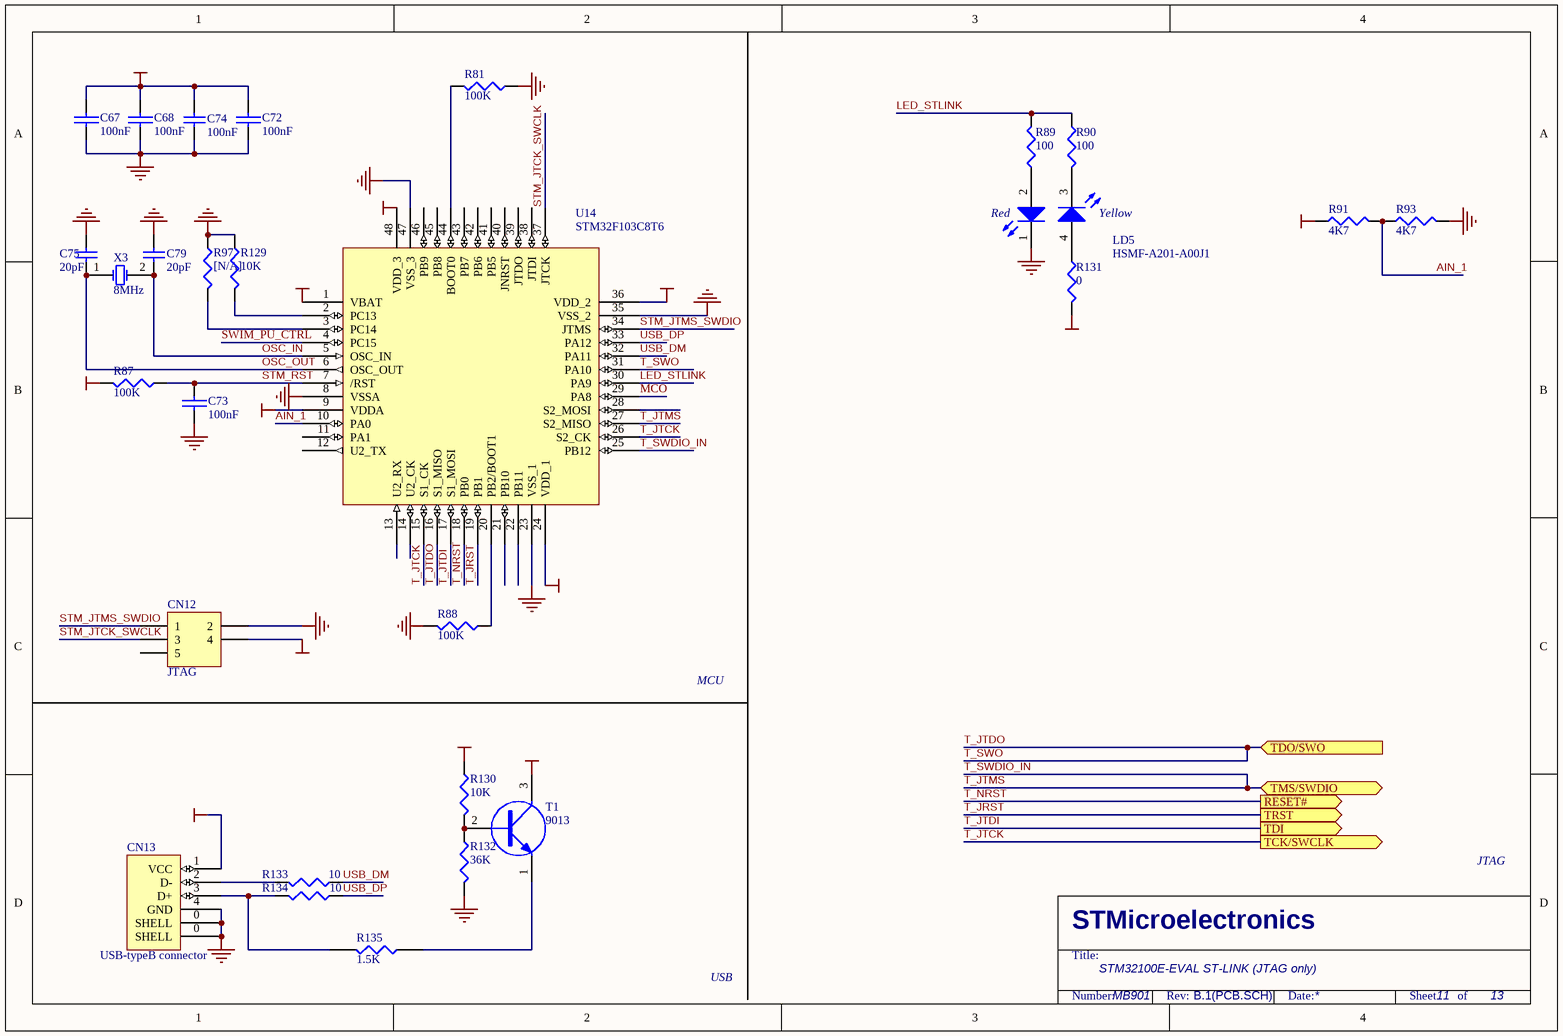
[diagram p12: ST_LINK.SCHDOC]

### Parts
C67  100nF  [0402C]
C68  100nF  [0402C]
C72  100nF  [0402C]
C73  100nF  [0402C]
C74  100nF  [0402C]
C75  20pF  [0603C]
C79  20pF  [0603C]
CN12  JTAG  [2*3P]
CN13  USB-typeB connector  [USB-B]
LD5  HSMF-A201-A00J1
R81  100K  [0603R]
R87  100K  [0603R]
R88  100K  [0603R]
R89  100  [0603R]
R90  100  [0603R]
R91  4K7  [0603R]
R93  4K7  [0603R]
R97  [N/A]  [0603R]
R129  10K  [0402R]
R130  10K  [0402R]
R131  0  [0603R]
R132  36K  [0603R]
R133  10  [0603R]
R134  10  [0603R]
R135  1.5K  [0603R]
T1  9013  [SOT-23]
U14  STM32F103C8T6  [LQFP48]
X3  8MHz  [SMT_XTAL]

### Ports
RESET# (out), TCK/SWCLK (out), TDI (out), TDO/SWO (in), TMS/SWDIO (bidir), TRST (out)

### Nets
+3V3: C67.2 C68.2 C72.2 C74.1 CN12.4 R87.2 R91.1 R131.2 T1.3(C) U14.1(VBAT) U14.9(VDDA) U14.24(VDD_1) U14.36(VDD_2) U14.48(VDD_3)
GND: C67.1 C68.1 C72.1 C73.1 C74.2 C75.1 C79.1 CN12.2 CN13.0(SHELL) CN13.4(GND) LD5.1(RED_cathode) R81.1 R88.2 R93.2 R97.1 R129.1 R132.2 U14.8(VSSA) U14.23(VSS_1) U14.35(VSS_2) U14.47(VSS_3)
U5V_ST_LINK: CN13.1(VCC) R130.1
AIN_1: R91.2 R93.1 U14.10(PA0)
LED_STLINK: R89.2 R90.1 U14.30(PA9)
MCO: U14.29(PA8)
OSC_IN: C79.2 U14.5(OSC_IN) X3.2(OSC2)
OSC_OUT: C75.2 U14.6(OSC_OUT) X3.1(OSC1)
STM_JTCK_SWCLK: CN12.3 U14.37(JTCK)
STM_JTMS_SWDIO: CN12.1 U14.34(JTMS)
STM_RST: C73.2 R87.1 U14.7(/RST)
SWIM_PU_CTRL: U14.4(PC15)
T_JRST: U14.19(PB1) ; port TRST  [project net PB4]
T_JTCK: U14.15(S1_CK) U14.26(S2_CK) ; port TCK/SWCLK  [project net PA14]
T_JTDI: U14.17(S1_MOSI) ; port TDI  [project net PA15]
T_JTDO: U14.16(S1_MISO) U14.31(PA10) ; port TDO/SWO  [also labelled T_SWO]  [project net PB3]
T_JTMS: U14.25(PB12) U14.27(S2_MISO) ; port TMS/SWDIO  [also labelled T_SWDIO_IN]  [project net PA13]
T_NRST: U14.18(PB0) ; port RESET#  [project net RESET#]
USB_DM: R133.1 U14.32(PA11)
USB_DP: R134.1 U14.33(PA12)
NetCN13_2: CN13.2(D-) R133.2
NetCN13_3: CN13.3(D+) R134.2 R135.2
NetLD5_2: LD5.2(Red_anode) R89.1
NetLD5_3: LD5.3(YellowGreen_cathode) R90.2
NetLD5_4: LD5.4(YellowGreen_anode) R131.1
NetR81_2: R81.2 U14.44(BOOT0)
NetR88_1: R88.1 U14.20(PB2/BOOT1)
NetR97_2: R97.2 U14.3(PC14)
NetR129_2: R129.2 U14.2(PC13)
NetR130_2: R130.2 R132.1 T1.2(B)
NetR135_1: R135.1 T1.1(E)

Not connected (* = marked no-connect by the designer): CN12 5; U14 11(PA1) 12(U2_TX) 13(U2_RX) 14(U2_CK) 21(PB10) 22(PB11) 28(S2_MOSI) 38(JTDI) 39(JTDO) 40(JNRST) 41(PB5) 42(PB6) 43(PB7) 45(PB8) 46(PB9)

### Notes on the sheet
- MCU
- JTAG
- USB
- STM32100E-EVAL ST-LINK (JTAG only)
- MB901
- 11
- 13

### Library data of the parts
C67 C68 C72 C73 = CAP
C74 = Cap: Capacitor; Value: 10nF
C75 C79 = Cap: Capacitor
CN12 = Header 3X2: Header, 3-Pin, Dual row
R81 R87-R91 R93 R131 R133-R135 = RES1
R97 R129 R130 R132 = R: Right: 20; Bottom: 30
T1 = NPN
U14 = STM32F10x(48pin)
X3 = XTAL: Crystal Oscillator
